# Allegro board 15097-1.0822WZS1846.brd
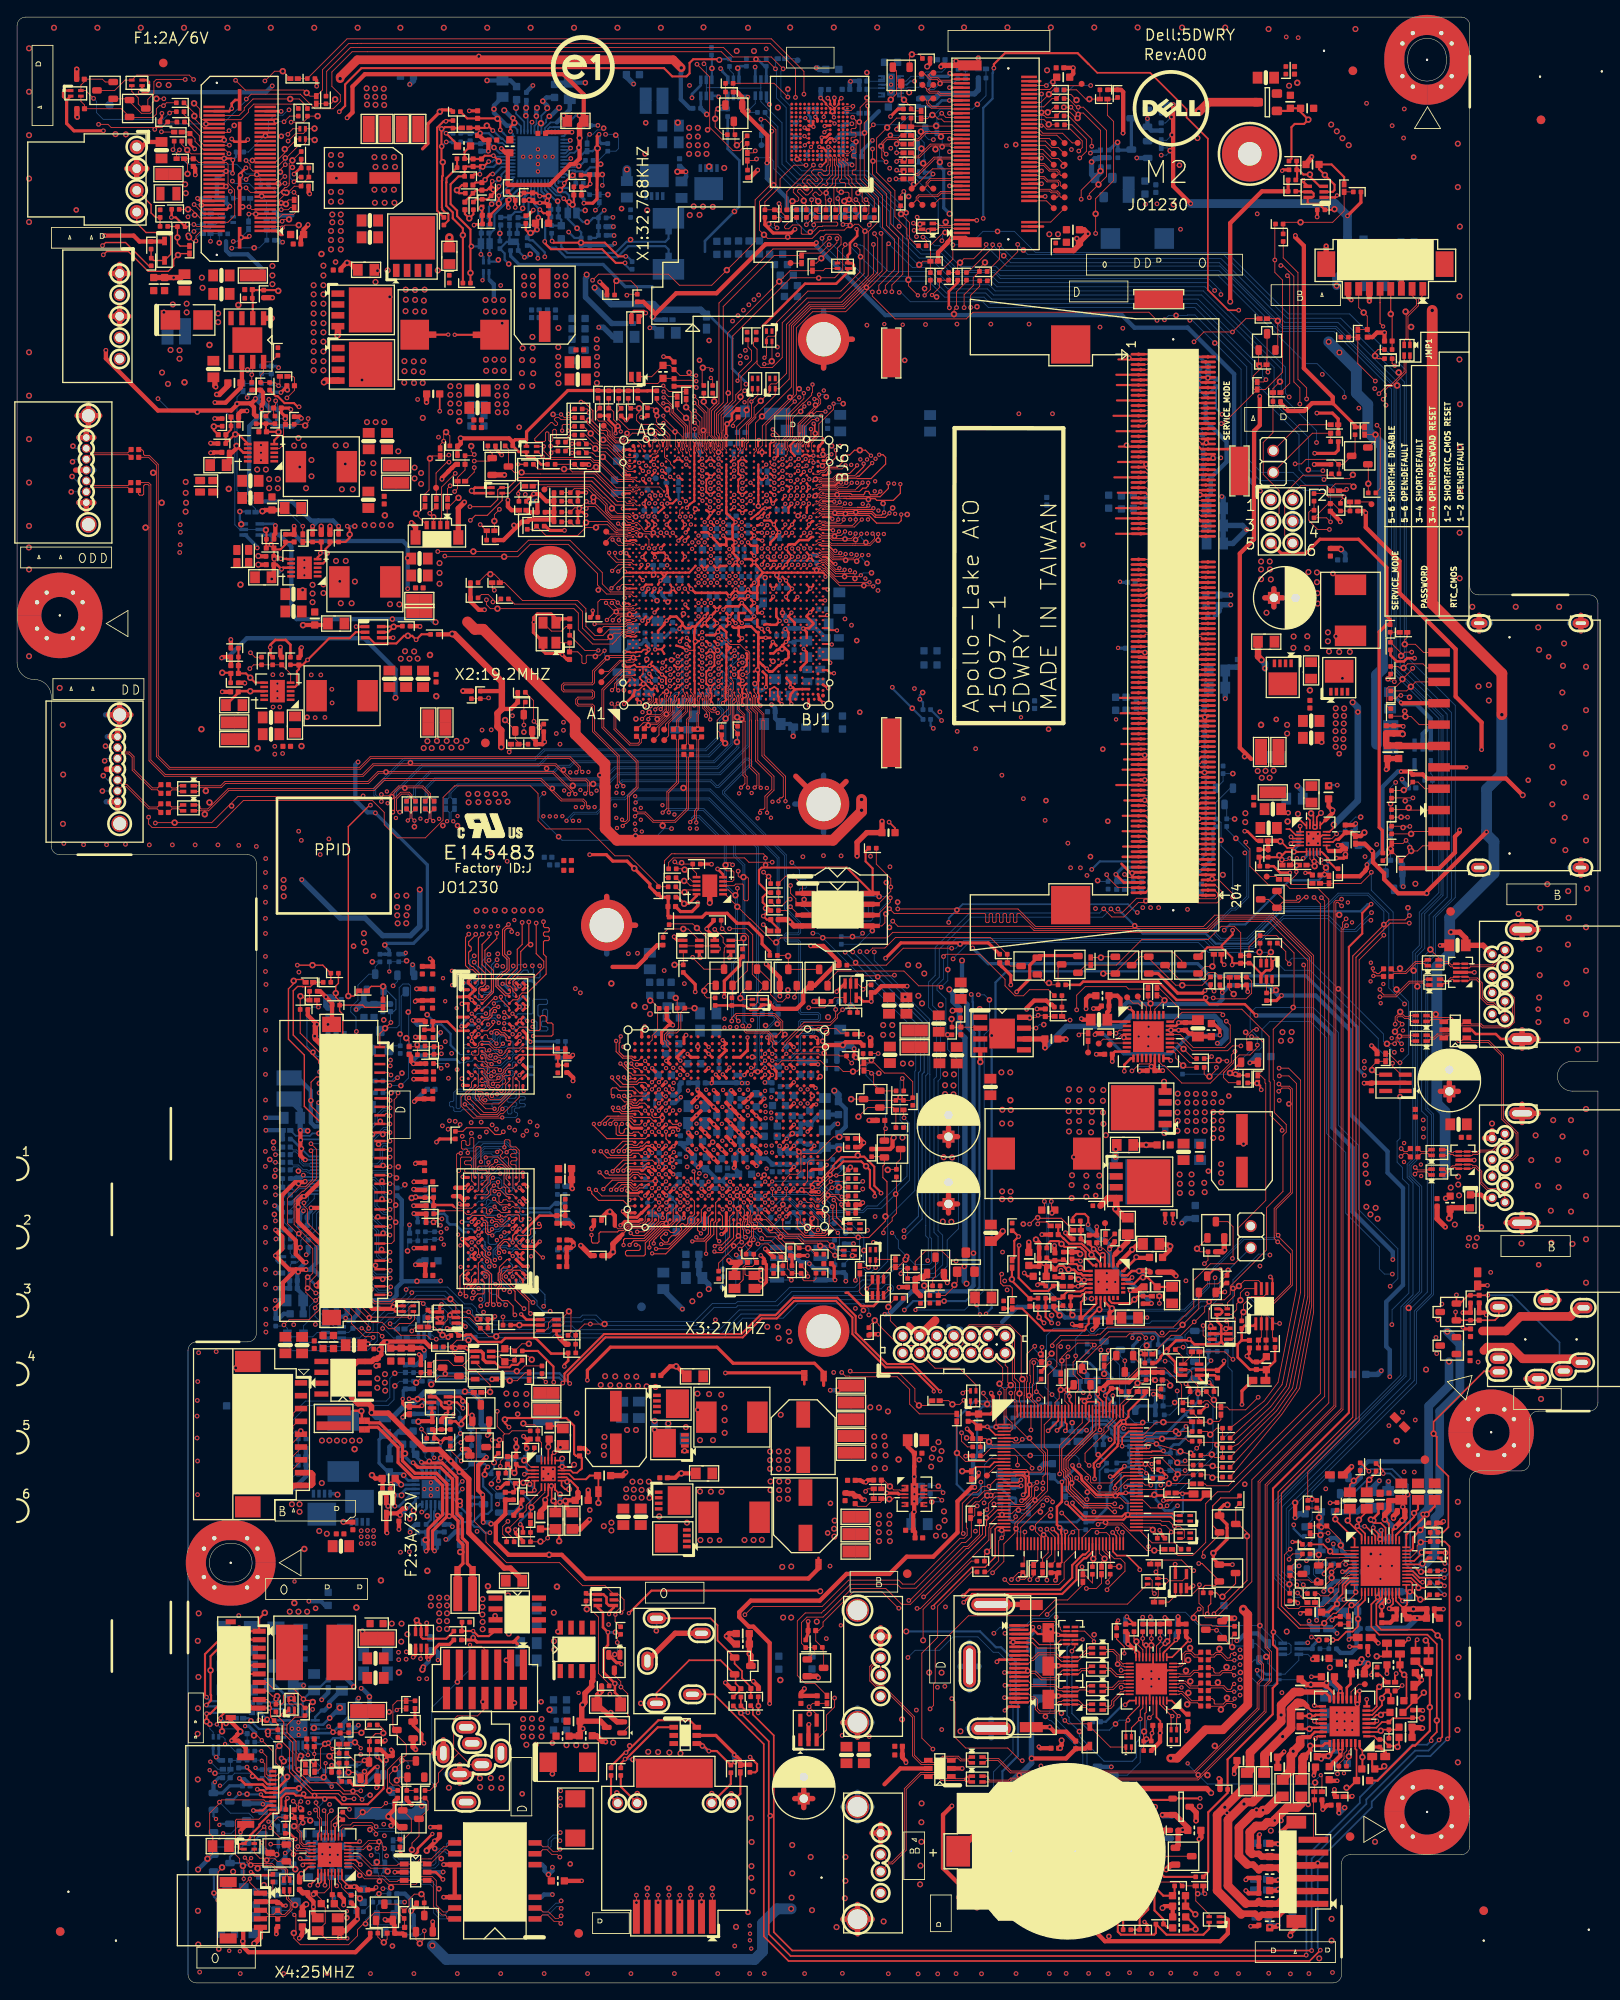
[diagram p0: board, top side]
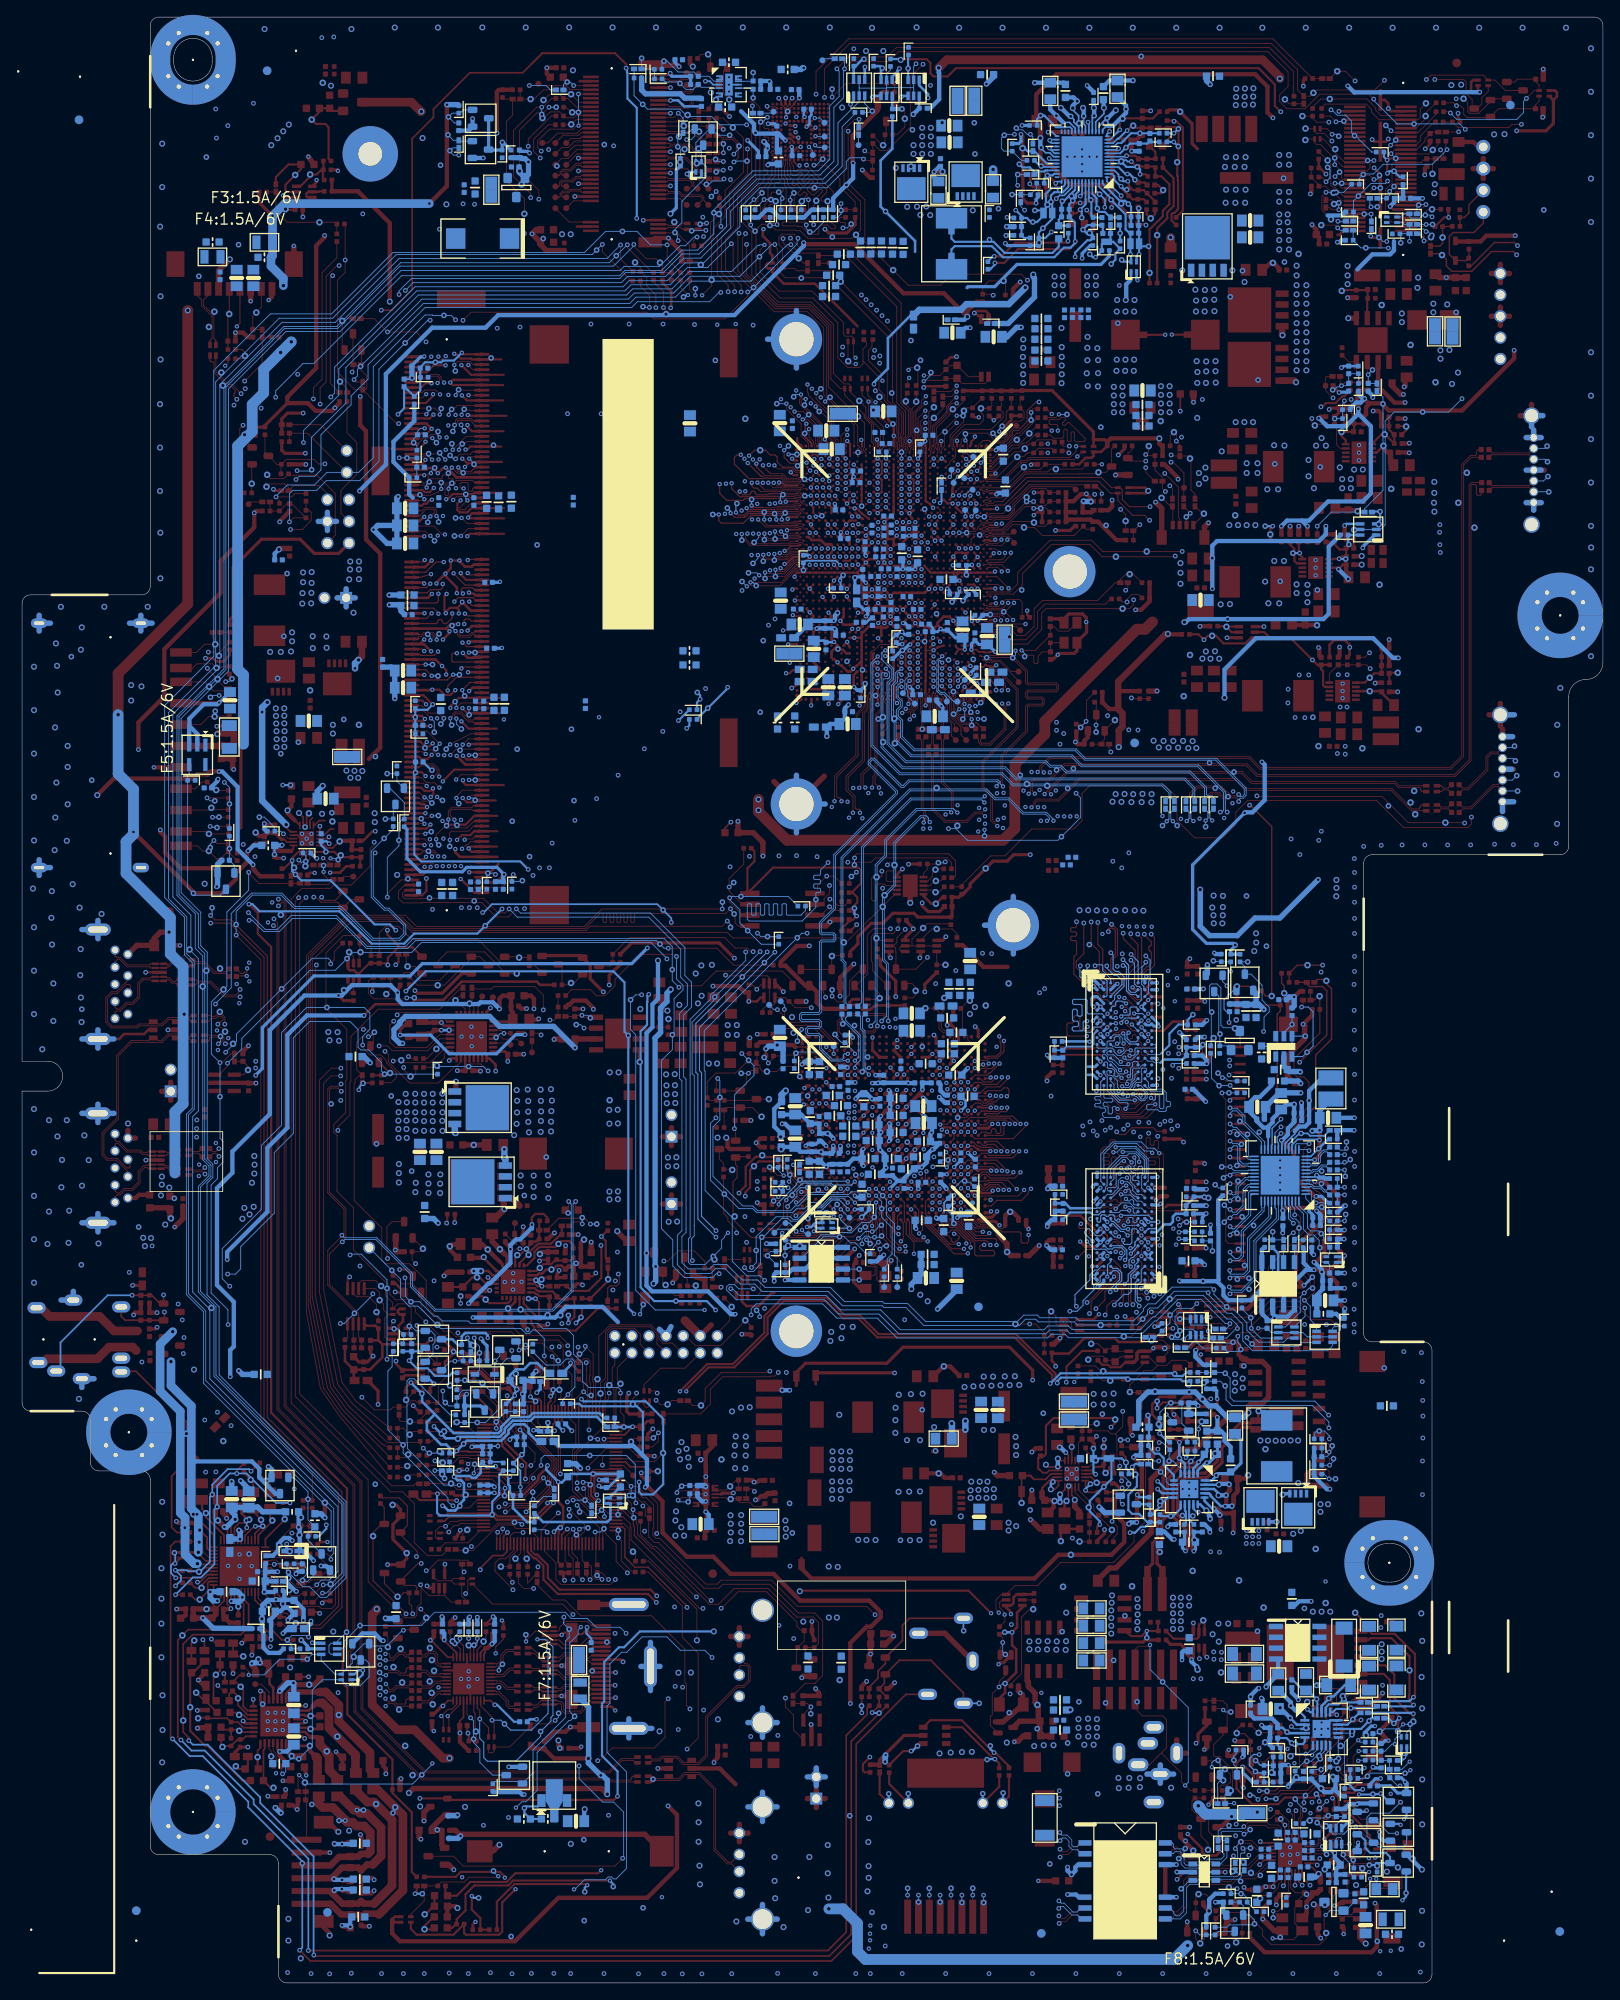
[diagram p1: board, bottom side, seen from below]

Outline 185 x 230 mm; copper layers: TOP, L2VCC, L3, L4, L5GND, BOTTOM. Coordinates in mm from the lower left corner of the outline.
Outline path: 0,229 0,154.5 arc(0.59,153.09) 2,152.5 arc(3.41,151.91) 4,150.5 4,133 arc(4.29,132.29) 5,132 27,132 arc(27.71,131.71) 28,131 28,76 arc(27.71,75.29) 27,75 21,75 arc(20.29,74.71) 20,74 20,1 arc(20.29,0.29) 21,0 154,0 arc(154.71,0.29) 155,1 155,14 arc(155.29,14.71) 156,15 169,15 arc(169.71,15.29) 170,16 170,58.9 arc(170.29,59.61) 171,59.9 176,59.9 arc(176.71,60.19) 177,60.9 177,65.9 arc(177.29,66.61) 178,66.9 184,66.9 arc(184.71,67.19) 185,67.9 185,104.34 182,104.34 arc(180.25,106.09) 182,107.84 185,107.84 185,161.4 arc(184.71,162.11) 184,162.4 171,162.4 arc(170.29,162.69) 170,163.4 170,229 arc(169.71,229.71) 169,230 1,230 arc(0.29,229.71) 0,229 ; 24.75,51.4 25.25,51.4 arc(27.5,49.15) 25.25,46.9 24.75,46.9 arc(22.5,49.15) 24.75,51.4 ; 162.75,225.25 arc(165,227.5) 167.25,225.25 167.25,224.75 arc(165,222.5) 162.75,224.75 162.75,225.25

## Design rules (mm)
constraint set DEFAULT: min track width 0.127, pair gap 0.102
net group AGND: nets CHG_AGND EC_AGND
net group AUDIO_IO_15: nets LINEOUT-L LINEOUT-R
net group AUDIO_SPK_L_C: nets SPKR_L+_C SPKR_L-_C
net group AUDIO_SPK_R_C: nets SPKR_R+_C SPKR_R-_C
net group AUDIO_SPKR_OUT_L: nets SPKR_OUT_L+ SPKR_OUT_L-
net group AUDIO_SPKR_OUT_R: nets SPKR_OUT_R+ SPKR_OUT_R-
net group CHARGER_4_5_MW-MW: nets AC_PROTECT AC_PROTECT_R
net group EMMC_RESET: nets EMMC_RESET# EMMC_RESET#_R
net group GPU_SMBUS: nets SMB_CLK_GPU SMB_DAT_GPU
net group INT_SERIRQ_CPU: nets INT_SERIRQ_CPU SER_IRQ
net group LAN_MDI2_DN: nets LAN_MDI2_DN LAN_MDI2_DN_R
net group LAN_MDI2_DP: nets LAN_MDI2_DP LAN_MDI2_DP_R
net group LAN_MDI3_DN: nets LAN_MDI3_DN LAN_MDI3_DN_R
net group LAN_MDI3_DP: nets LAN_MDI3_DP LAN_MDI3_DP_R
net group POWER_30_25: nets PWR_5V_HG1 PWR_VDDQ_HG
net group SATAHDR_RX_DN1: nets SATA__RXN1_C SATAHDR_RX_DN1
net group SATAHDR_RX_DP1: nets SATA__RXP1_C SATAHDR_RX_DP1
net group SATAHDR_TX_DN1: nets SATA__TXN1_C SATAHDR_TX_DN1
net group SATAHDR_TX_DP1: nets SATA__TXP1_C SATAHDR_TX_DP1
net group SIDE_USB3_TX0+: nets USB30_TX_CPU_P0 USB30_TX_CPU_P0_EMI
net group SIDE_USB3_TX0-: nets USB30_TX_CPU_N0 USB30_TX_CPU_N0_EMI
net group SIDE_USB3_TX1+: nets USB30_TX_CPU_P1 USB30_TX_CPU_P1_EMI
net group SIDE_USB3_TX1-: nets USB30_TX_CPU_N1 USB30_TX_CPU_N1_EMI
net group SIO_EUP: nets SIO_EUP_EN# SIO_EUP_EN#_G
net group SPI_CLK: nets KBC_SPI_CLK SPI_CLK_KBC_MUX
net group SPI_CLK-MW: nets ROM_SCLK ROM_SCLK_R
net group SVID-MW: nets VR_SVID_CLK VR_SVID_DATA
net group USB5_TP: nets USB_DN5 USB_DP5
net group USB_OC-MW: nets USBOC01 USBOC02
net group VGA_OTHER: nets +V_1P05_VGA_DISCHIG +V_1P35_VGA_DISCHG
net group AUDIO_AMP_10: nets AMP_SPKR_L AMP_SPKR_R SPKR_IN_L SPKR_IN_R TPA3131_LINN TPA3131_LINN_1 TPA3131_RINN TPA3131_RINN_1
net group AUDIO_AMP_15: nets PORTC_SPK_L PORTC_SPK_L_1 PORTC_SPK_R PORTC_SPK_R_1 TPA3131_GAIN TPA3131_GVDD TPA3131_MUTE TPA3131_PLIMIT
net group AUDIO_DMIC: nets AUD_DMIC_CLK AUD_DMIC_CLK_R AUD_DMIC_CLK_R_1 AUD_DMIC_DATA AUD_DMIC_DATA_R
net group AUDIO_HDA-15-MW: nets AUD_LINK_BCLK
net group AUDIO_HDA-MW: nets APU_SPKR AUD_BEEP_C AUD_BEEP_R AUD_LINK_RST_N AUD_LINK_RST_N_2 AUD_LINK_RST_N_R AUD_LINK_SDIN AUD_LINK_SDIN_1 AUD_LINK_SDIN_ST AUD_LINK_SDO AUD_LINK_SDO_1 AUD_LINK_SDO_N AUD_LINK_SYNC AZ_BCLK_M AZ_RST_N_M AZ_RST_R_M AZ_SDIN_M AZ_SDOUT_M AZ_SYNC_M BUZZER_SPKR_R PCH_AUD_RST_N PCH_AUD_RST_N_1 SENSE_B SLEEVE_G SPKR_DET_C
net group AUDIO_IO: nets AUD_GP3 EAPD_DEPOP HPOL_CON HPOR_CON HPOUT-JD HPOUT-L HPOUT-R LINE2-VREFO LINEOUT-JD LINEOUT_C-L LINEOUT_C-R LINEOUT_CON-L LINEOUT_CON-R MIC2-L MIC2-L-1 MIC2-R MIC2-R-1 MIC2-VREFO-L MIC2-VREFO-R
net group AUDIO_IO_REF: nets JDREF MIC-CAP VRP
net group AUDIO_POP-MW: nets TPA3131_FAULT# TPA3131_SD TPA3131_SD1#
net group AUDIO_SPK_CN: nets SPKR_L+_SNB SPKR_L-_SNB SPKR_R+_SNB SPKR_R-_SNB TPA3131_BSNL TPA3131_BSNR TPA3131_BSPL TPA3131_BSPR
net group CARDREADER-MW: nets SD_PWR_EN SD_PWR_EN_CPU# SD_PWR_EN_CPU#_R
net group CHARGER_4-5_MW-MW: nets AC_IN AC_IN_KBC#_R BAT_ALERT BAT_IN# BAT_IN#_1 CHG_ON# PD4405_A PD4405_K PQ4406_2 PQ4406_3 PQ4406_5 PQ4406_6 PQ4409_C PQ4409_E SYS_PRES
net group CLOCK-MW: nets CK_25M_SIO LPC_CLK0_R LPC_CLK1 LPC_CLK1_R SUSCLK SUSCLK_SIO_C XTAL19D2M_IN XTAL19D2M_OUT
net group CONERTER_4-5_MW-MW: nets LEDC_ISET LPF RT SSTCMP SSTCMP_1 STATUS
net group CONVERTER_10_10: nets ISEN1 ISEN2 ISEN3 ISEN4 ISW OZ554_PWM RTN1 RTN2 RTN3 RTN4
net group CONVERTER_20_10: nets LDR LDR_1 OZ554_VIN VREF
net group CPU_CRITITAL-MW: nets APU_PROCHOT# APU_PROCHOT#_R LPC_PME_N PMC_BATLOW#
net group DBG_I2C_SCL_LB: nets DBG_I2C_SCL_LB M1_SMB_CLK SMB0_CLK_MAIN SMB0_CLK_RESUME
net group DBG_I2C_SDA_LB: nets DBG_I2C_SDA_LB M1_SMB_DATA SMB0_DATA_MAIN SMB0_DATA_RESUME
net group DDR3_VREF: nets M_A_VREFCA_CPU M_A_VREFDQ_CPU PWR_VDDQ_VTTREF VREF_CA_DIMM1 VREF_DQ_DIMM1
net group DEEPSLEEP-MW: nets SUS_PWR_ACK_CPU
net group DP1_TXN0: nets DP1_TXN0 DP_CPU_TXN0 DP_CPU_TXN2 DRX0N
net group DP1_TXN1: nets DP1_TXN1 DP_CPU_TXN1 DP_CPU_TXN3 DRX1N
net group DP1_TXP0: nets DP1_TXP0 DP_CPU_TXP0 DP_CPU_TXP2 DRX0P
net group DP1_TXP1: nets DP1_TXP1 DP_CPU_TXP1 DP_CPU_TXP3 DRX1P
net group EC_CRITITAL: nets EC_SCI# EC_SMI# EC_SWI# ECRST# ECSCI#_KBC ECSMI#_KBC ECSWI#_KBC GPIO_11_SCI GPIO_12_SWI RTCRST_ON VNN_CTRL
net group EC_OTHER: nets EC_BEEP_GPIO EC_BEEP_GPIO_EC EC_DEBUG EC_PECI EDID_WC# EDID_WC_EC# PMIC_THERMTRIP#_EC RTC_DET# VD1_EN#
net group EC_PSL: nets PSL_IN1# PSL_IN2# PSL_OUT#
net group EC_PWR_12_12: nets EC_AVCC EC_VBKUP EC_VCC1V8_S5 EC_VCC3 EC_VDD3D3 EC_VSBY EC_VTT KBC_VCC
net group EC_SMB: nets EC_SMB_DATA
net group EC_SPI: nets EC_SPI_CS0_N EC_SPI_SI EC_SPI_SO
net group EC_SPI_CLK: nets EC_SPI_CLK
net group EC_VD: nets VD_IN1 VD_IN2 VD_OUT1# VD_OUT2#
net group EDP_PWM: nets BKLT_ADJ CPU_LVDS_BL_ADJ DPLVDS_PWMIN DPLVDS_PWMOUT LVDS_BL_ADJ RTD_LVDS_BL_ADJ SIO_LVDS_BL_ADJ
net group EMMC_CLK: nets EMMC_CLK
net group EMMC_CMD: nets EMMC_CMD
net group EMMC_DATA_0: nets EMMC_DATA_0
net group EMMC_DATA_1: nets EMMC_DATA_1
net group EMMC_DATA_2: nets EMMC_DATA_2
net group EMMC_DATA_3: nets EMMC_DATA_3
net group EMMC_DATA_4: nets EMMC_DATA_4
net group EMMC_DATA_5: nets EMMC_DATA_5
net group EMMC_DATA_6: nets EMMC_DATA_6
net group EMMC_DATA_7: nets EMMC_DATA_7
net group EMMC_POWER: nets EMMC_VDDI
net group EMMC_RCLK: nets EMMC_RCLK
net group EMMC_TP: nets EMMC_E9 EMMC_E10 EMMC_F10 EMMC_K10
net group FAN_PWM: nets CPU_FAN_CTRL_SIO CPU_FAN_TACH_SIO SYS_FAN_TACH1_1 SYS_FAN_TACH1_2 SYSTEM_FAN_PWM1_1
net group GPIO-MW: nets BATT_AMBER_LED# BATT_AMBER_LED#_C BATT_WHITE_LED# BATT_WHITE_LED#_C BIST_DISABLE BIST_DISABLE_1 BIST_EN BIST_EN_INV BIST_EN_SIO BIST_ENABLE BIST_ENABLE_1 BIST_PIN25 EAPD_DEPOP_1 EC_IMS JACK_PSID LVDS_DET_A* LVDS_DET_B* LVDS_PU_5 LVDS_PU_5_1 LVDS_PU_6 LVDS_PU_24 MINI_POWER_CTRL MPCIE_DISABLE_N NGFF_BT_DISABLE NGFF_DETECT_PCIE NGFF_DETECT_PCIE_C NGFF_DETECT_USB NGFF_DETECT_USB_C OSD_BIST_N OSD_DN OSD_DN_R OSD_MENU OSD_MENU_R OSD_UP OSD_UP_R PCB_VER_ID PSID_D PSID_D_1 PSID_G PW_CLEAR PW_CLEAR_H SOC_EXTSMI_N SPKR_DET WEBCAM_DET WEBCAM_DET_M
net group GPU_GPIO: nets GPIO1_FBVDDQCTL GPIO2_BL_PWM GPIO3_PPEN_R GPIO4_BLEN GPIO5_PWM_VID_BOOT_EN GPIO6_FB_CLAMP_TGL_REQ GPIO7_3D_STEREO GPIO8_OVERT# GPIO9_ALERT# GPIO10_MEM_VREF_CTL GPIO11_PWM_VID GPIO12_AC_DETECT GPIO13_NVVDD_PSI GPIO123_CPU
net group GPU_OTHER_4-6-MW: nets FB_VREF FBA_DEBUG0 FBA_DEBUG1 GC6_FB_EN GPIO_FB_CLAMP_GPU GPU_DMINUS GPU_DMINUS_G GPU_DPLUS GPU_DPLUS_G GPU_TESTMODE GPU_THERM_SHUTDOWN_N GPU_VCC3_CTL_2 GPU_WAKEB_CPU IFPA_IOVDD IFPAB_PLLVDD_1 IFPAB_PLLVDD_2 IFPB_IOVDD IFPC_IOVDD IFPC_PLLVDD_1 IFPC_PLLVDD_2 IFPD_IOVDD IFPD_PLLVDD_1 IFPD_PLLVDD_2 IFPE_IOVDD IFPEF_PLLVDD_1 IFPEF_PLLVDD_2 IFPF_IOVDD JTAG_TCLK JTAG_TDI JTAG_TDO JTAG_TMS JTAG_TRST PEX_TERMP PEX_TSTCLK_OUT PEX_TSTCLK_OUT# STRAP0 STRAP1 STRAP2 STRAP3 STRAP4 STRAP_REF0
net group GPU_VREF: nets DACA_VREF PWR_VGA_CORE_VREF PWR_VGA_CORE_VREF_1 PWR_VGA_CORE_VREF_2 VREFC_U20 VREFC_U21 VREFC_U22 VREFC_U23 VREFD_U20 VREFD_U21 VREFD_U22 VREFD_U23
net group GPU_ZQ: nets U15_ZQ U19_ZQ U35_ZQ U36_ZQ
net group HDMI1_DATA_IC_N0: nets HDMI1_DATA_IC_N0 HDMI_DATA_CPU_N0 HDMI_LANE0_IC_DN
net group HDMI1_DATA_IC_N1: nets HDMI1_DATA_IC_N1 HDMI_DATA_CPU_N1 HDMI_LANE1_IC_DN
net group HDMI1_DATA_IC_N2: nets HDMI1_DATA_IC_N2 HDMI_DATA_CPU_N2 HDMI_LANE2_IC_DN
net group HDMI1_DATA_IC_N3: nets HDMI1_DATA_IC_N3 HDMI_DATA_CPU_N3 HDMI_LANE3_DN HDMI_LANE3_IC_DN
net group HDMI1_DATA_IC_P0: nets HDMI1_DATA_IC_P0 HDMI_DATA_CPU_P0 HDMI_LANE0_DP HDMI_LANE0_IC_DP
net group HDMI1_DATA_IC_P1: nets HDMI1_DATA_IC_P1 HDMI_DATA_CPU_P1 HDMI_LANE1_DP HDMI_LANE1_IC_DP
net group HDMI1_DATA_IC_P2: nets HDMI1_DATA_IC_P2 HDMI_DATA_CPU_P2 HDMI_LANE2_DP HDMI_LANE2_IC_DP
net group HDMI1_DATA_IC_P3: nets HDMI1_DATA_IC_P3 HDMI_DATA_CPU_P3 HDMI_LANE3_IC_DP
net group HDMI_MW: nets CFG DCIN_EN DDCBUF DDPC_CTRL_CLK_CONN DDPC_CTRL_DATA_CONN EQ HDMI_CTRL_CLK HDMI_CTRL_CLK_CPU HDMI_CTRL_DATA HDMI_CTRL_DATA_CPU ISET PRE REXT
net group HPD-MW: nets CPU_HPD DDSP_C_HPD_CONN DP1_HPD DP_HPD DPLVDS_HPD HDM2_CPU_HPD HDMI2_HPD HDMI_DP2_HPD MODEL_ID_DET
net group LAN_OTHER_4-5-MW: nets LAN_RSET LANCLK_REQ_U_N RTL_ISOLATE_N RTL_ISOLATE_N_1 RTL_ISOLATE_N_2
net group LED_10_6: nets APU_SATA_LED_B APU_SATA_LED_N LAN_LEDACT_R# LINK_ACTIVITY_N LINK_PWR PB_IN_SW1 PCH_SATA_LED_1 PWR_LED_YELLOW_C PWR_LED_YELLOW_C2 SIO_GREEN_PWM SIO_HDD_LED SIO_HDD_LED_1 SIO_YELLOW SPEED_100*_CON SPEED_100_N SPEED_1000*_CON SPEED_1000_N SUS_LED_GREEN_C SUS_LED_GREEN_C2
net group LPC-MW: nets INIT_3V LPC_PME_N_R TPM_CLKRUN_N TPM_GPIO0 TPM_GPIO1 TPM_GPIO2 TPM_GPIO3 TPM_LCLK TPM_LPCPD_N TPM_PP TPM_RST_N TPM_SERIRQ
net group MIPI: nets CX_PMODE_PLRST_N DBG7_R DBG16_R DBG_H_PRDY_N DBG_H_PREQ_N DBG_H_TCK DBG_H_TDI DBG_H_TDO DBG_H_TMS DBG_H_TRST_N DBG_PMU_PLTRST_N DBG_PMU_PWRBTN_N DBG_PMU_RSTBTN_N DBG_PTI_CLK0 DBG_RSMRST_N DBG_TARGET_PRESENT_N DBG_UART_RXD DBG_UART_TXD DFX_MSR_STRAP GP_SPI0_FS1 TRST_PD
net group NGFF_CLK-MW: nets NGFF_CLKREQ0_N NGFF_CLKREQ1_N SUSCLK_NGFF
net group NGFF_OTHER-MW: nets NGFF_ALERT_N NGFF_PEWAKE0_N NGFF_POWER_CTRL_1 NGFF_POWER_CTRL_V2 NGFF_W_DISABLE1_N NGFF_W_DISABLE2_N SMB0_ALERT#_C
net group OCSILLATION-MW: nets LAN_XTALI LAN_XTALO PCH_RTCRST PCH_RTCRST_DOWN PCH_RTCRST_PULLUP PCH_RTCX1 PCH_RTCX2 PCH_SRTCRST_DOWN PCH_SRTCRSTB_PULLUP XTAL_OUTBUFF XTAL_SSFOUT
net group OTHERS-MW: nets 1D8V_EMMC_CT1 1D8V_EMMC_EN 3D3V_EMMC_CT2 3D3V_EMMC_EN AC_PRESENT_KBC AD_IA_R AD_JK1 AD_OFF_L ADAPTOR_PSID_R_R ALERT# AMD_RST#_L CLKA0_AND CLKA1_AND DIMM1_SA0 DIMM1_SA1 DISCHANGE_EN DPLVDS_HPD_1 GLAN_WAKE_CPU GLAN_WAKE_N GLAN_WAKE_N_LS GPIO34_CPU GPIO35_CPU GPIO36_VCCIO_LEVEL GPIO39_TXE_BPS GPIO40_CPU GPIO43_EMMC_BOOT GPIO44_SPI_BOOT GPIO47_DNXFW GPIO48_CPU GPIO78_SMB_LEVEL GPIO82_CPU GPIO88_PMU_LEVEL GPIO92_SMB_NRB GPIO104_CPU GPIO105_CPU GPIO110_LPC_LEVEL GPIO111_BBS GPIO112_CPU GPIO113_CPU GPIO117_CPU GPIO118_FLASH_OVR GPIO120_BIOS_SWAP GPIO121_CPU GPU_PEX_RST_HOLD GPU_PEX_RST_HOLD_GPU# H_PROCHOT_N_EC INTRUDER KBC_ON#_GATE KBC_ON#_GATE_L KBC_VCORF LVDS_PU_6_2 ME_UNLOCK ME_UNLOCK_1 ME_UNLOCK_2 ME_UNLOCK_3 MEM_MA_EVENT_L MIPI_PMODE NCT3956_OE#_MUX NGFF_WAKE_CPU NGFF_WAKE_N NGFF_WAKE_N_LS OSD_BIST_N_LS OSD_MENU_EC OSD_MENU_LS PCH_PCIECLKRQ0_N PCH_PCIECLKRQ1_N PCH_PCIECLKRQ3_N PCH_PCIECLKRQ3_N_B PCIE_WAKE1# PEX_RST_GPU_D# PLTRST#_CPU_D PLTRST#_EC_R PLTRST#_LPC PLTRST_N_1 PM_SLP_S0#_CPU PMIC_I2C_SCL PMIC_I2C_SDA PMIC_THERMTRIP# PMU_WAKE#_EMMC PNL0_BKLCTL PNL1_BKLCTL PURE_HW_SHUTDOWN#_R PWRBTN_APS PWRGD_3V_D S5_ENABLE SD_WP_BD_CPU SIO_EUP_EN_D SIO_GREEN_PWM_1 SIO_MEM_EVENT_L SIO_MEM_EVENT_L_B SIO_MEM_EVENT_L_C SIO_PWNBTN_N SLP_S0_APS SLP_S3_N_APS SLP_S4_N_APS SLP_S4_N_EC SOC_PWROK_CPU SRTCRST_APS SYS_PEX_RST_MON_GPU# SYS_PWRGD_G T_CRIT# THERM_SYS_SHDN# USB_EN_1 USB_EN_2 USB_OTGID USB_VBUSSNS V1P8A_S5_PG VCC3_CT2 VCC_CT1 VID_PLLVDD
net group PANEL_CONTROL: nets BKLT_EN BKLT_EN1 DPLVDS_BL_EN DPLVDS_PANEL_VCC LVDS_DET_B_C* PANEL_ON_1 PANEL_ON_2 PANEL_ON_3 PANEL_SEL1_CABLE PANEL_SEL1_CABLE_EC PANEL_SEL2_CABLE PANEL_SEL2_CABLE_EC PANEL_SEL3_CABLE PANEL_SEL3_CABLE_EC S_LVDS_BL_EN
net group PCIE_CLKREQ-MW: nets PCH_PCIECLKRQ2_N PCH_PCIECLKRQ2_N_1 PCH_PCIECLKRQ2_N_B PEX_CLKREQ_M PEX_CLKREQ_N
net group POWER: nets 3V_VA 19V_AMP_AVCC AD+_2 ADAPTOR_PSID_R AUD_DVDD AUD_REGREF AVCC33_2136 CBN CBP CPVEE DIGITAL_PU DPLVDS_PIN12 DPLVDS_PIN16 DVCC33_2136 EAPD_DEPOP_2 GND_AUD GPU_VCC3_CTL LED_5VSB OSD_BIST_N_1 PWRCN_DET_N PWRCN_DET_N_C SWR_LX SWR_V12 V_3P0_BAT_VREG V_5_CODEC VBAT1 VBAT1_R VREF_1 VREG_PCIAUX_PCH VREG_PCIAUX_PCH_1
net group POWER_10_10: nets 1D8V_S0_EN 1D8V_S0_EN1 1D8V_S0_EN2 1D8V_S0_EN_G 1D8V_SPI 1D35V_S3_PWRGD 1117_ADJ AD+_G_1 AD+_G_2 AD_IA AD_IA_HW1 AD_IA_HW2 EC_V_3P3_A GPU_ALLPWR NCP81172_FB1 PSYS PWR_1D05V_EN PWR_1D05V_FB PWR_1D05V_FB_N PWR_1D24V_EN PWR_1D24V_FB PWR_1D24V_FB_N PWR_1D24V_PG PWR_1D35V_FB PWR_1D35V_FB_N PWR_1P15V_PG_L PWR_3D3V_CS2 PWR_3D3V_FB2 PWR_3D3V_LDO3 PWR_5V_BOOT1_A PWR_5V_FB1 PWR_5V_LDO5 PWR_ALERT# PWR_CHG_ACDET PWR_CHG_ILIM PWR_CHG_NC PWR_SCLK_A PWR_SDIO PWR_V1P8A_FB PWR_V1P24A_PG_L PWR_VCCGI_COMP PWR_VCCGI_COMPA PWR_VCCGI_CSCOMP PWR_VCCGI_CSP1 PWR_VCCGI_CSREF PWR_VCCGI_CSSUM PWR_VCCGI_DIFFOUT PWR_VCCGI_EN PWR_VCCGI_EN_PH PWR_VCCGI_FB PWR_VCCGI_FBA PWR_VCCGI_ICCMAX PWR_VCCGI_ILIM PWR_VCCGI_IOUT PWR_VCCGI_NTC PWR_VCCGI_TSENSE PWR_VCCGI_VR_RDY PWR_VCCGI_VR_RDY1 PWR_VCCGI_VRMP PWR_VCCGI_VSN PWR_VCCGI_VSNA PWR_VCCGI_VSP PWR_VCCGT_ILIM_NTC PWR_VDDQ_FB PWR_VGA_CORE_COMP PWR_VGA_CORE_COMP_1 PWR_VGA_CORE_FB PWR_VGA_CORE_FBRTN PWR_VGA_CORE_FS PWR_VGA_CORE_PGOOD PWR_VGA_CORE_PSI PWR_VGA_CORE_PVCC PWR_VGA_CORE_REFIN PWR_VGA_CORE_SENSE+_1 PWR_VGA_CORE_TALERT# PWR_VGA_CORE_TSNS PWR_VGA_CORE_VID PWR_VGA_CORE_VIDBUF PWR_VGA_VRAM_POK PWR_VGA_VRAM_POK_B_1 PWR_VNN_COMP PWR_VNN_COMPA PWR_VNN_CSN_NTC PWR_VNN_CSP1B PWR_VNN_ILIM PWR_VNN_IOUT PWR_VNN_PWM PWR_VNN_VSN PWR_VNN_VSP PWR_VNN_VSPA PWR_VNN_VSPA_R PWR_VR_HOT# V_3P3_A V_5P0_A VNN_VCC_SENSE VNN_VSS_SENSE
net group POWER_10_15: nets BOOT_HALT_N
net group POWER_12_12: nets 3D3V_AUX_S5_MUX BUFRST_N PQ4206_D PWR_3D3V_BOOT2 PWR_3D3V_BOOT2_A
net group POWER_20_10: nets 3D3VDD_TPM PWR_1D05V_SVIN PWR_1D24V_SVIN PWR_VDDQ_VDD PWR_VDDQ_VDDQ PWR_VDDQ_VID PWR_VGA_CORE_BOOT1_1 PWR_VGA_CORE_LGATE1 PWR_VGA_CORE_SNB PWR_VGA_CORE_VCC VCC_1P24_A1_R
net group POWER_20_20: nets PWR_1D05V_SN PWR_1D24V_SN PWR_3D3V_FB2_A PWR_3D3V_SN PWR_5V_BOOT1 PWR_5V_BYP1 PWR_5V_FB1_A PWR_5V_SN PWR_CORE_BOOT PWR_CORE_BOOT_A PWR_CORE_SN PWR_VGA_CORE_BOOT1 PWR_VNN_BOOT PWR_VNN_BOOTA PWR_VNN_SN
net group POWER_25_20: nets CORE_PLLVDD DACA_VDD FB_CAL_PD_VDDQ FB_CAL_PU_GND FB_CAL_TERM_GND
net group POWER_50_10: nets 1D8V_S5_D 1D24V_DSI_CSI 1D24V_GLML 1D24V_S5_D 1P05V_S5_D BQ24737_REGN DC_IN_D PWR_1D35V_SVIN PWR_CHG_BTST PWR_CHG_BTST_1 PWR_CHG_CMPIN PWR_CHG_CMPIN_R PWR_CHG_CMPIN_RR PWR_CHG_VCC PWR_VCORE_VNN_D SB3V_D SP_PLLVDD
net group POWER_100_10: nets DCBATOUT_RT6575_1
net group POWER_OTHER: nets 3V3AUX ALL_PWRGD_2 PURE_HW_SHUTDOWN# PWR_CHG_AD_OFF PWR_CHG_AD_OFF_R PWR_VDDQ_CS PWR_VDDQ_TON PWRBTN_N_R PWRGD_3V_G1 PWRGD_3V_G2 PWRGD_3V_N
net group POWER_PHASE: nets PWR_CHG_HIDRV PWR_CHG_LODRV PWR_CORE_HG1 PWR_CORE_LG1 PWR_VGA_CORE_UGATE1 PWR_VGA_CORE_UGATE1_R PWR_VNN_HG
net group PWR-EN_MW-MW: nets 1D8V_S0_EN_R DGPU_PWR_EN# GPU_1D05V_EN GPU_1D05V_FB GPU_1D05V_VGA_EN PWR_3D3V_EN2 PWR_5V3V_EMN_R PWR_5V_EN1 PWR_V1P8A_EN PWR_VDDQ_EN PWR_VGA_CORE_EN PWR_VTT_EN SIO_EUP_EN#_L SIO_EUP_EN#_R SIO_GPU_EN_C SIO_GPU_EN_LS SLP_S0_N SLP_S3_N SLP_S4_N VCC3_EN VCC_EN VGA_CORE_DISCHG VTT_EN VTT_EN_R
net group PWRGD-RST-MW: nets 1P05V_PG 1P05V_PG_EC 3V_5V_POK AC_PRESENT_CPU APU_PWNBTN_N APU_PWNBTN_N_R DDR3_DRAMRST_N DDR3_DRAMRST_N_A_1 GPU_1D05V_PG LAN_DISABLE_N LAN_DISABLE_N_1 LAN_DISABLE_N_2 LAN_DISABLE_N_3 LAN_DISABLE_N_4 LAN_DISABLE_V3 OZ554_ENA PCIE_RST# PEX_RST_GPU PLT_RST#_CPU PLTRST*_SIO PLTRST_LAN_N PLTRST_N PLTRST_N_1A PLTRST_N_R PLTRST_SL_N PM_SLP_S3#_CPU PM_SLP_S4#_CPU PMC_SUS_STAT PSTBTN_N PSTBTN_N_APS PWR_3D3V_5V_PG PWR_5V_CS1 PWR_V1P8A_PG PWRBTN_N PWRGD_3V PWRGD_3V_B PWRGD_3V_B_1 PWRGD_3V_C PWRGD_3V_LL PWROK3_1_R PWROK3_2_R RSMRST#_KBC_MUX RSMRST*_R RSMRST_APS RSMRST_N SIO_GPU_EN SIO_GPU_RST SIO_GPU_RST_C SIO_GPU_RST_LS SLP_S3_N_EC SUS_PWR_ACK_CPU_R SYS_PWRGD V1P8A_S5_PG_EC WAKE_N_APU
net group SATAHDR_RX_DN0: nets SATA__RXN0_C SATAHDR_RX_DN0 SATAHDR_RX_DN0_EMI
net group SATAHDR_RX_DP0: nets SATA__RXP0_C SATAHDR_RX_DP0 SATAHDR_RX_DP0_EMI
net group SATAHDR_TX_DN0: nets SATA__TXN0_C SATAHDR_TX_DN0 SATAHDR_TX_DN0_EMI
net group SATAHDR_TX_DP0: nets SATA__TXP0_C SATAHDR_TX_DP0 SATAHDR_TX_DP0_EMI
net group SD_CD_BD: nets SD_CD_BD_CPU
net group SD_CLK_BD: nets SD_CLK_BD_CPU
net group SD_CMD_BD: nets SD_CMD_BD_CPU
net group SD_DATA0_BD: nets SD_DATA0_CPU
net group SD_DATA1_BD: nets SD_DATA1_CPU
net group SD_DATA2_BD: nets SD_DATA2_CPU
net group SD_DATA3_BD: nets SD_DATA3_CPU
net group SIDE_USB3_RX0+: nets USB30_RX_CPU_P0
net group SIDE_USB3_RX0-: nets USB30_RX_CPU_N0
net group SIDE_USB3_RX1+: nets USB30_RX_CPU_P1
net group SIDE_USB3_RX1-: nets USB30_RX_CPU_N1
net group SIO_IT8732-MW: nets EC_HDMI_PD_N IMS SW_ON_N_SIO
net group SIO_OTHERS-MW: nets AC_OK# ADAPTOR_PSID_SIO INT_SERIRQ_OE PD_N
net group SMBUS-MW: nets BATA_SCL_1 BATA_SDA_1 DPLVDS_EDIDCLK DPLVDS_EDIDCLK_C DPLVDS_EDIDSDA DPLVDS_EDIDSDA_C DPLVDS_FWCLK DPLVDS_FWSDA DPLVDS_ISPCLK DPLVDS_ISPDAT I2CC_SCL_PU I2CC_SDA_PU I2CS_SCL_G I2CS_SDA_G ISP_CLK1 ISP_DAT1 NCT_CLK NCT_DATA PWR_CHG_IOUT SIO_SMCLK0 SIO_SMCLK0_D SIO_SMDAT0 SIO_SMDAT0_D SMB0_ALERT# SMB0_CVT_CLK SMB0_CVT_DATA SMBUS_ISP SMBUS_ISP_G
net group SPI-MW: nets FWH_ID0
net group SPI_CLK_CPU_MUX: nets SPI_CLK_CPU_MUX SPI_CLK_N_CPU SPI_CLK_ROM SPI_CLK_ROM_CPU SPI_CLK_ROM_KBC SPI_CLK_ROM_MUX
net group SPI_CS0_N_ROM: nets SPI_CS0_N_ROM_CPU SPI_CS0_R_CPU SPI_CS_CPU_MUX SPI_CS_ROM_MUX
net group SPI_DATA: nets KBC_SPI_CS0_N KBC_SPI_DATAIN KBC_SPI_DATAOUT ROM_CS* ROM_CS_R* ROM_SI ROM_SI_R ROM_SO SPI_CS0_N_ROM_KBC SPI_CS_KBC_MUX SPI_DATAIN_N_CPU SPI_DATAIN_ROM SPI_DATAOUT_N_CPU SPI_DATAOUT_ROM SPI_IO2_N_CPU SPI_IO2_ROM SPI_IO3_N_CPU SPI_IO3_ROM
net group SVID0_CLK_CPU: nets SVID0_CLK_CPU_R
net group SVID0_DATA_ALERT: nets SVID0_ALERT#_CPU_R SVID0_DATA_CPU_R VR_SVID_ALERT#
net group TP-MW: nets AC_IN_KBC# SYNC TP_DET TP_NGFF_COEX1 TP_NGFF_COEX2 TP_NGFF_COEX3 TP_NGFF_LED1 TP_NGFF_LED2 TP_NGFF_MLDIR
net group TRANSFORNER_20_10: nets XRF_TDC2
net group UART: nets LPSS_UART1_RXD LPSS_UART2_CTS# LPSS_UART2_RTS# LPSS_UART2_RXD LPSS_UART2_TXD
net group WLAN_CLINK_MW-MW: nets CLINK_CLK_LAN CLINK_DATA_LAN CLINK_RST_LAN_N
net group XDP-MW: nets DBG0 DBG1 DBG2 DBG3 DBG4 DBG5 DBG6 DBG7 DBG16 TAP_PRDY# TAP_PREQ# XDP_H_TDO XDP_H_TRST_N
net group XTAL_GPU_27MHZ: nets XTALOUT_GPU

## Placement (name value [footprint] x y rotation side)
AFTP1  AFTE14P-GP  [AFTE14P-75]  43.92 26.54 0 top
BAT2  ACES-CON9-10-GP  [51202-00901-W01-U]  27 64.2 270 top
BT1  BAT-AAA-BAT-034-K01-GP  [AAA-BAT-034-K01]  116.34 15.4 180 top
C1  SCD1U16V2KX-3DLGP  [C402H22]  122.04 224.07 90 top
C2  SCD1U16V2KX-3DLGP  [C402H22]  149.49 223.77 0 top
C3  SC10U6D3V3MX-DL-GP  [C603H36]  122.42 222.97 270 top
C4  SC10U10V5KX-2GP  [C805H54]  146.13 222.91 270 top
C5  SCD1U50V3KX-GP  [C603H36]  149 220.09 180 top
C6  SCD1U50V3KX-DL-GP  [C603H35]  150.96 219.33 90 top
C7  SCD1U16V2KX-3DLGP  [C402H22]  20.22 215.93 0 top
C8  SC10U25V5KX-DL-GP  [C805H58]  16.9 214.43 180 top
C9  SCD1U16V2KX-3DLGP  [C402H22]  20.61 212.97 0 top
C10  SCD1U50V3KX-GP  [C603H36]  151.6 212.76 270 top
C11  SC2D2U10V3KX-1DLGP-U  [C603H36]  123.56 205.12 90 top
C12  SC10U6D3V3MX-DL-GP  [C603H36]  32.77 204.56 90 top
C13  SC10U6D3V3MX-DL-GP  [C603H36]  123.56 203.65 270 top
C14  SCD1U16V2KX-3DLGP  [C402H22]  32.76 203.45 90 top
C15  SC10U10V5KX-2DLGP  [C805H50]  19.59 198.96 180 top
C16  SC1U50V3KX-1-GP  [C603H36]  15.99 198.76 180 top
C17  SC10U6D3V3MX-DL-GP  [C603H36]  17.26 198.76 180 top
C18  SC100P50V2JN-3GP  [C402H22]  160.47 192.1 90 top
C19  SC1U10V2KX-1DLGP  [C402H22]  65.85 191.07 90 top
C20  SC22U6D3V5MX-2DLGP  [C805H54]  65.61 189.63 90 top
C21  SC2D7P50V2CN-3-GP  [C402H22]  76.88 189.2 180 top
C22  SC22U6D3V5MX-2DLGP  [C805H54]  65.61 187.6 90 top
C23  SC2D7P50V2CN-3-GP  [C402H22]  76.88 187.25 0 top
C24  SC22U6D3V5MX-2DLGP  [C805H54]  53.88 186.31 270 top
C25  SC22U6D3V5MX-2DLGP  [C805H54]  53.88 184.28 270 top
C26  SCD1U16V2KX-3DLGP  [C402H22]  84.37 183.65 180 top
C27  SC1U10V2KX-1DLGP  [C402H22]  53.9 182.86 270 top
C28  SC1U10V2KX-1DLGP  [C402H22]  53.89 181.98 270 top
C29  SC1U10V2KX-1DLGP  [C402H22]  154.16 181.32 90 top
C30  SCD01U50V2KX-1DLGP  [C402H22]  13.79 179.41 270 top
C31  SCD01U50V2KX-1DLGP  [C402H22]  13.79 178.49 270 top
C32  SC47P50V2JN-3GP  [C402H22]  51.98 177.67 270 top
C33  SCD01U50V2KX-1DLGP  [C402H22]  13.75 175.53 270 top
C34  SCD01U50V2KX-1DLGP  [C402H22]  13.75 174.62 270 top
C35  SC1U10V2KX-1DLGP  [C402H22]  153.68 172.63 0 top
C36  SC3D3P50V2CN-DL-GP  [C402H22]  64.67 159.15 0 top
C37  SC3D3P50V2CN-DL-GP  [C402H22]  64.65 155.29 180 top
C38  SCD1U16V2KX-3DLGP  [C402H22]  160.22 146.64 0 top
C39  SCD1U16V2KX-3DLGP  [C402H22]  161.12 146.64 0 top
C40  SCD1U16V2KX-3DLGP  [C402H22]  72.49 146.29 0 top
C41  SCD1U16V2KX-3DLGP  [C402H22]  73.4 146.29 0 top
C42  SCD22U10V2KX-2-GP  [C402H22]  76.83 146.24 0 top
C43  SCD22U10V2KX-2-GP  [C402H22]  79.21 146.24 0 top
C44  SCD22U10V2KX-2-GP  [C402H22]  80.1 146.23 0 top
C45  SCD22U10V2KX-2-GP  [C402H22]  77.71 146.23 0 top
C46  SCD1U16V2KX-3DLGP  [C402H22]  78.03 144.17 0 top
C47  SCD1U16V2KX-3DLGP  [C402H22]  78.91 144.17 0 top
C48  SC4D7U6D3V3KX-DLGP  [C603H36]  161.68 144.01 180 top
C49  SC4D7U6D3V3KX-DLGP  [C603H36]  160.36 144 180 top
C50  SCD01U50V2KX-1DLGP  [C402H22]  17.27 140.19 270 top
C51  SCD01U50V2KX-1DLGP  [C402H22]  17.27 139.18 270 top
C52  SC1U10V2KX-1DLGP  [C402H22]  144.72 138.26 0 top
C53  SCD01U50V2KX-1DLGP  [C402H22]  17.26 137.96 270 top
C54  SCD01U50V2KX-1DLGP  [C402H22]  17.26 136.94 270 top
C55  SC22U6D3V5MX-2DLGP  [C805H54]  75.62 82.14 180 bottom
C56  SCD1U16V2KX-3DLGP  [C402H22]  76.61 125.93 90 top
C57  SCD1U16V2KX-3DLGP  [C402H22]  88.64 124.41 270 top
C58  SC100P50V2JN-3DLGP  [C402H22]  143.2 119.74 0 top
C59  SC10U10V5KX-2DLGP  [C805H50]  168.56 121.4 90 top
C60  SCD1U16V2KX-3DLGP  [C402H22]  160.36 118.64 90 top
C61  SCD1U16V2KX-3DLGP  [C402H22]  47.42 118.49 180 top
C62  SCD1U16V2KX-3DLGP  [C402H22]  48.64 118.49 180 top
C63  SCD1U16V2KX-3DLGP  [C402H22]  160.36 117.75 90 top
C64  SCD1U16V2KX-3GP  [C402H22]  142.34 116.69 90 top
C65  SC1U10V2KX-1DLGP  [C402H22]  48.08 116.3 270 top
C66  SC1U10V2KX-1DLGP  [C402H22]  48.62 114.5 180 top
C67  SC1U10V2KX-1DLGP  [C402H22]  47.43 114.49 180 top
C68  SC22U6D3V5MX-2DLGP  [C805H54]  102.04 114.35 180 top
C69  SC22U6D3V5MX-2DLGP  [C805H54]  104.07 114.35 180 top
C70  SCD1U16V2KX-3DLGP  [C402H22]  127.34 114.29 270 top
C71  SC1U50V3KX-1-GP  [C603H36]  77.14 88.67 0 bottom
C72  SC10U10V5KX-2DLGP  [C805H50]  126.61 112.69 270 top
C73  SCD1U16V2KX-3DLGP  [C402H22]  48.21 112.47 270 top
C74  SCD1U16V2KX-3DLGP  [C402H22]  136.74 111.91 180 top
C75  SC10U10V5KX-2DLGP  [C805H50]  138.18 111.68 180 top
C76  SCD01U50V2KX-1DLGP  [C402H22]  99.45 109.7 90 top
C77  SCD01U25V2KX-3LLGP  [C402H22]  45.87 109.09 0 top
C78  SCD1U16V2KX-3DLGP  [C402H22]  127.72 108.66 270 top
C79  SC22U6D3V5MX-2DLGP  [C805H54]  102.14 108.58 0 top
C80  SCD1U16V2KX-3DLGP  [C402H22]  63.73 108.35 90 top
C81  SCD1U16V2KX-3GP  [C402H22]  159.15 108.27 180 top
C82  SCD1U16V2KX-3DLGP  [C402H22]  132.7 106.73 270 top
C83  SC1U10V2KX-1DLGP  [C402H22]  48.29 106.6 270 top
C84  SCD1U16V2KX-3DLGP  [C402H22]  48.29 105.74 270 top
C85  SC1U10V2KX-1DLGP  [C402H22]  158.49 104.82 180 top
C86  SC1U10V2KX-1DLGP  [C402H22]  48.64 103.88 0 top
C87  SCD1U16V2KX-3DLGP  [C402H22]  47.63 103.87 0 top
C88  SCD1U16V2KX-3DLGP  [C402H22]  163.62 101.75 0 top
C89  SC100P50V2JN-3DLGP  [C402H22]  101.1 100.91 90 top
C90  SC10U10V5KX-2DLGP  [C805H50]  168.69 100.46 90 top
C91  SCD1U16V2KX-3GP  [C402H22]  169.45 98.93 270 top
C92  SCD1U16V2KX-3DLGP  [C402H22]  163.49 97.62 270 top
C93  SCD1U50V3KX-DL-GP  [C603H35]  138.41 97.23 180 top
C94  SCD1U16V2KX-3DLGP  [C402H22]  163.48 96.65 270 top
C95  SC1U10V2KX-1DLGP  [C402H22]  47.68 95.49 180 top
C96  SC10U6D3V3MX-DL-GP  [C603H36]  64.12 95.26 90 top
C99  SC1U10V2KX-1DLGP  [C402H22]  166.17 91.31 0 top
C100  SC10U6D3V3MX-DL-GP  [C603H36]  64.12 93.98 90 top
C101  SC1U10V2KX-1DLGP  [C402H22]  48.19 93.73 270 top
C103  SCD1U16V2KX-3DLGP  [C402H22]  48.31 90.93 270 top
C104  SCD1U16V2KX-3DLGP  [C402H22]  63.17 89.33 0 top
C108  SC22U6D3V5MX-2DLGP  [C805H54]  113.95 87.76 0 top
C110  SCD1U16V2KX-3DLGP  [C402H22]  63.9 86.92 90 top
C111  SCD1U16V2KX-3DLGP  [C402H22]  63.9 86 90 top
C112  SCD1U16V2KX-3DLGP  [C402H22]  48.26 85.97 270 top
C113  SC1U10V2KX-1DLGP  [C402H22]  63.88 84.94 90 top
C114  SC15P50V2JN-DL-GP  [C402H22]  85.03 84.3 270 top
C115  SC15P50V2JN-DL-GP  [C402H22]  86.98 84.3 90 top
C116  SCD1U16V2KX-3-LL-GP  [C402H22]  94.85 84.15 270 top
C117  SC1U10V2KX-1DLGP  [C402H22]  48.21 84.02 270 top
C118  SC1U10V2KX-1DLGP  [C402H22]  63.88 83.82 90 top
C119  SC1U10V2KX-1DLGP  [C402H22]  48.21 82.77 270 top
C120  SCD01U25V2KX-3DLGP  [C402H22]  104.66 81.41 90 top
C121  SC100P50V2JN-3DLGP  [C402H22]  171.1 80.01 0 top
C122  SCD1U16V2KX-3DLGP  [C402H22]  107.81 79.98 0 top
C123  SC100P50V2JN-3DLGP  [C402H22]  171.1 77.98 180 top
C124  SC100P50V2JN-3DLGP  [C402H22]  170.09 76.07 180 top
C125  SC2200P50V2KX-2DLGP  [C402H22]  145.71 75.21 90 top
C126  SCD1U16V2KX-3DLGP  [C402H22]  144.21 74.73 0 top
C127  SC470P50V2KX-3DLGP  [C402H22]  145.71 74.3 90 top
C128  SCD1U25V3KX-DLGP  [C603H36]  43.73 73.52 180 top
C129  SCD1U25V3KX-DLGP  [C603H36]  44.95 73.52 180 top
C130  SCD1U25V3KX-DLGP  [C603H36]  46.14 73.52 180 top
C131  SC100P50V2JN-3DLGP  [C402H22]  170.04 73.25 0 top
C132  SC10U6D3V3MX-DL-GP  [C603H36]  146.19 72.5 180 top
C133  SCD1U16V2KX-3DLGP  [C402H22]  145.03 72.21 180 top
C134  SCD1U16V2KX-3DLGP  [C402H22]  140.48 71.23 180 top
C135  SCD1U10V2KX-5GP  [C402H22]  133.1 71 0 top
C136  SCD1U16V2KX-3DLGP  [C402H22]  134.01 70.99 180 top
C137  SCD1U16V2KX-3DLGP  [C402H22]  127.61 69.56 270 top
C138  SCD1U16V2KX-3DLGP  [C402H22]  137.96 66.8 90 top
C139  SCD1U10V2KX-5DLGP  [C402H22]  111.3 66.15 180 top
C140  SC2D2U10V3KX-1DLGP-U  [C603H36]  112.51 65.8 180 top
C141  SC220P50V2KX-3GP  [C402H22]  112.28 63.68 270 top
C142  SC10U10V5KX-2GP  [C805H54]  105.19 63.5 270 top
C143  SCD1U16V2KX-3DLGP  [C402H22]  105.44 61.98 270 top
C144  SC1U6D3V2KX-DLGP  [C402H22]  100.69 58.83 270 top
C145  SC10U10V5KX-2DLGP  [C805H50]  161.98 57.48 180 top
C146  SC10U10V5KX-2DLGP  [C805H50]  163.94 57.48 0 top
C147  SC10U10V5KX-2DLGP  [C805H50]  165.9 57.48 0 top
C148  SCD1U16V2KX-3DLGP  [C402H22]  160.54 56.87 0 top
C149  SC2D2U10V3KX-1DLGP-U  [C603H36]  159.51 56.53 180 top
C150  SC1U6D3V2KX-DLGP  [C402H22]  98.08 56.52 180 top
C151  SC10U10V5KX-2DLGP  [C805H50]  155.96 56.44 180 top
C152  SC10U10V5KX-2DLGP  [C805H50]  157.94 56.44 180 top
C153  SCD1U16V2KX-3DLGP  [C402H22]  161.96 55.24 90 top
C155  SCD1U25V2KX-GP  [C402H22]  152.81 53.47 90 top
C156  SC1U10V2KX-1DLGP  [C402H22]  104.43 52.96 90 top
C157  SCD1U16V2KX-3DLGP  [C402H22]  105.53 52.07 270 top
C158  SC22P50V2JN-4GP  [C402H22]  154.21 48.87 90 top
C159  SC1U10V2KX-1DLGP  [C402H22]  120.99 48.44 0 top
C160  SCD1U16V2KX-3DLGP  [C402H22]  121.91 48.44 0 top
C161  SC100P50V2JN-3DLGP  [C402H22]  148.95 48.11 0 top
C162  SCD1U16V2KX-3DLGP  [C402H22]  165.41 43.76 90 top
C163  SCD1U16V2KX-3DLGP  [C402H22]  161.88 43.74 270 top
C164  SC10U6D3V3MX-DL-GP  [C603H36]  151.9 43.38 90 top
C165  SC10U6D3V3MX-GP  [C603H38]  162.01 42.7 270 top
C166  SC10U6D3V3MX-DL-GP  [C603H36]  165.69 42.67 270 top
C167  SC1U10V2KX-1DLGP  [C402H22]  159.7 42.6 0 top
C168  SC100P50V2JN-3GP  [C402H22]  154.85 42.42 0 top
C169  SCD1U16V2KX-3DLGP  [C402H22]  129.74 41.54 0 top
C170  SCD1U16V2KX-3DLGP  [C402H22]  135.91 41.54 180 top
C171  SCD01U50V2KX-1DLGP  [C402H22]  136.8 41.54 180 top
C172  SC33P50V2JN-3DLGP  [C402H22]  93.02 41.22 270 top
C173  SC1KP50V2KX-1GP  [C402H22]  157.61 39.34 90 top
C174  SCD1U16V2KX-3DLGP  [C402H22]  138.96 38.69 270 top
C175  SC10U25V5KX-DL-GP  [C805H58]  41.94 37.97 90 top
C176  SCD1U16V2KX-3DLGP  [C402H22]  138.96 37.81 270 top
C177  SCD1U16V2KX-3DLGP  [C402H22]  138.96 36.89 270 top
C178  SC1U50V3KX-1-GP  [C603H36]  156.9 36.17 90 top
C179  SCD1U16V2KX-3DLGP  [C402H22]  138.96 36 270 top
C180  SCD1U50V3KX-DL-GP  [C603H35]  153.4 35.81 270 top
C181  SC10U25V5KX-DL-GP  [C805H58]  41.94 35.69 90 top
C182  SCD1U16V2KX-3DLGP  [C402H22]  138.96 35.09 270 top
C183  SCD22U25V3KX-DL-GP  [C603H36]  150.15 34.8 0 top
C184  SC100P50V2JN-3DLGP  [C402H22]  86.32 34.44 270 top
C185  SC100P50V2JN-3DLGP  [C402H22]  84.26 34.42 90 top
C186  SCD1U16V2KX-3DLGP  [C402H22]  138.96 34.2 270 top
C187  SC100P50V2JN-3DLGP  [C402H22]  160.82 34.16 270 top
C188  SCD1U16V2KX-3DLGP  [C402H22]  138.96 33.28 270 top
C189  SC1U10V2KX-1DLGP  [C402H22]  91.73 33.15 180 top
C190  SCD1U16V2KX-3GP  [C402H22]  93.63 33.15 180 top
C191  SCD027U50V3KX-DL-GP  [C603H36]  161.53 33.02 270 top
C192  SCD1U16V2KX-3DLGP  [C402H22]  138.96 32.39 270 top
C193  SCD22U25V3KX-DL-GP  [C603H36]  150.15 32 180 top
C194  SCD027U50V3KX-DL-GP  [C603H36]  161.42 31.65 270 top
C195  SCD1U16V2KX-3DLGP  [C402H22]  137.03 31 0 top
C196  SCD1U16V2KX-3DLGP  [C402H22]  133.35 30.12 270 top
C197  SC1U50V3KX-1-GP  [C603H36]  162.48 29.92 270 top
C198  SCD01U50V2KX-1DLGP  [C402H22]  37.8 29.69 180 top
C199  SCD22U25V3KX-DL-GP  [C603H36]  150.15 29.21 0 top
C200  SC1U50V3KX-1-GP  [C603H36]  162.48 28.73 270 top
C201  SCD1U25V2KX-LL-GP  [C402H22]  33.89 28.09 180 top
C202  SCD1U25V2KX-LL-GP  [C402H22]  34.78 28.09 180 top
C203  SCD1U16V2KX-3DLGP  [C402H22]  123.88 27.84 0 top
C204  SCD1U16V2KX-3DLGP  [C402H22]  103.16 27.69 90 top
C205  SCD01U50V2KX-1DLGP  [C402H22]  121.45 27.46 270 top
C206  SCD1U16V2KX-3GP  [C402H22]  41.69 27.28 90 top
C207  SC10U10V5KX-2GP  [C805H54]  97.06 26.67 0 top
C208  SC10U10V5KX-2GP  [C805H54]  99.09 26.67 0 top
C209  SCD1U16V2KX-3GP  [C402H22]  103.16 26.67 90 top
C210  SCD22U25V3KX-DL-GP  [C603H36]  151.39 26.47 270 top
C211  SCD68U16V3KX-GP-U  [C603H36]  146.74 26.42 90 top
C212  SCD68U16V3KX-GP-U  [C603H36]  143.52 26.01 270 top
C213  SCD68U16V3KX-GP-U  [C603H36]  151.19 25.25 90 top
C214  SCD68U16V3KX-GP-U  [C603H36]  148.29 25.22 270 top
C215  SCD027U50V3KX-DL-GP  [C603H36]  158.13 25.03 270 top
C216  SCD1U50V3KX-DL-GP  [C603H35]  153.55 24.54 0 top
C217  SCD027U50V3KX-DL-GP  [C603H36]  157.51 23.67 270 top
C218  SCD1U16V2KX-3DLGP  [C402H22]  154.21 20.8 270 top
C219  SCD1U16V2KX-3DLGP  [C402H22]  32.42 19.81 180 top
C220  SCD1U16V2KX-3DLGP  [C402H22]  33.31 19.81 180 top
C221  SCD01U50V2KX-1DLGP  [C402H22]  49.44 17.78 180 top
C222  SC1KP50V2KX-1DLGP  [C402H22]  145.32 15.54 180 top
C223  SC1KP50V2KX-1DLGP  [C402H22]  145.32 12.73 0 top
C224  SCD1U16V2KX-3DLGP  [C402H22]  33.05 11.38 180 top
C225  SCD1U16V2KX-3DLGP  [C402H22]  40.6 10.89 270 top
C226  SC12P50V2JN-DL-GP  [C402H22]  34.45 10.54 270 top
C227  SC15P50V2JN-DL-GP  [C402H22]  37.33 10.33 90 top
C228  SC1KP50V2KX-1DLGP  [C402H22]  145.32 10.03 180 top
C229  SC10P50V2JN-4GP  [C402H22]  30.5 8.94 180 top
C230  SC2D2U10V3KX-1DLGP-U  [C603H36]  33.38 7.32 0 top
C231  SC1KP50V2KX-1DLGP  [C402H22]  145.32 7.21 0 top
C232  SC10P50V2JN-4GP  [C402H22]  30.5 7.03 0 top
C233  SC1U10V2KX-1GP  [C402H22]  45.35 6.05 0 top
C234  SC1U10V2KX-1GP  [C402H22]  43.75 5.82 90 top
C235  SC1U10V2KX-1DLGP  [C402H22]  108.15 225.01 270 bottom
C236  SC1U6D3V2KX-DLGP  [C402H22]  106.31 223.08 270 bottom
C237  SC1KP50V2KX-1DLGP  [C402H22]  99 222.52 90 bottom
C238  SC1U6D3V2KX-DLGP  [C402H22]  106.31 222.12 270 bottom
C239  SC1KP50V2KX-1DLGP  [C402H22]  99 221.55 90 bottom
C240  SCD1U16V2KX-3DLGP  [C402H22]  97 221.55 270 bottom
C241  SCD1U16V2KX-3DLGP  [C402H22]  94.52 221.52 90 bottom
C242  SC1U10V2KX-1DLGP  [C402H22]  105.5 220 180 bottom
C243  SC4D7U6D3V2MX-1-GP  [C402H22]  93.07 219.23 270 bottom
C244  SC1U10V2KX-1GP  [C402H22]  133.89 217.17 180 bottom
C245  SCD1U16V2KX-3DLGP  [C402H22]  96.66 216.81 0 bottom
C246  SC1U10V2KX-1GP  [C402H22]  126.78 214 0 bottom
C247  SC4D7U6D3V2MX-1-GP  [C402H22]  94.44 213.78 270 bottom
C248  SC1U10V2KX-1DLGP  [C402H22]  98.39 213.68 90 bottom
C249  SC2D2U10V3KX-1DLGP-U  [C603H36]  131.99 210.06 180 bottom
C250  SCD1U16V2KX-3DLGP  [C402H22]  133.26 209.93 180 bottom
C251  SCD1U16V2KX-3DLGP  [C402H22]  22.95 208.79 90 bottom
C252  SC22U6D3V3MX-1-DL-GP  [C603H40]  86.87 203.05 0 bottom
C253  SC22U6D3V3MX-1-DL-GP  [C603H40]  85.66 203.05 0 bottom
C254  SC22U6D3V3MX-1-DL-GP  [C603H40]  84.43 203.05 0 bottom
C255  SC22U6D3V3MX-1-DL-GP  [C603H40]  83.13 203.03 0 bottom
C256  SC22U6D3V3MX-1-DL-GP  [C603H40]  81.89 203 0 bottom
C257  SC22U6D3V3MX-1-DL-GP  [C603H40]  88.83 202.26 270 bottom
C258  SC22U6D3V3MX-1-DL-GP  [C603H40]  89.39 201.04 270 bottom
C259  SC22U6D3V3MX-1-DL-GP  [C603H40]  90.08 199.8 270 bottom
C260  SCD1U16V2KX-3DLGP  [C402H22]  161.83 199.73 0 bottom
C261  SC10U10V5KX-2DLGP  [C805H50]  159.88 199.48 180 bottom
C262  SC10U10V5KX-2GP  [C805H54]  157.93 199.48 180 bottom
C263  SC22U6D3V3MX-1-DL-GP  [C603H40]  90.56 198.58 270 bottom
C264  SC22U6D3V3MX-1-DL-GP  [C603H40]  90.56 197.31 270 bottom
C265  SC1U10V2KX-1DLGP  [C402H22]  62.07 195.3 0 bottom
C266  SC1U10V2KX-1DLGP  [C402H22]  61.09 195.3 0 bottom
C267  SC1U10V2KX-1DLGP  [C402H22]  60.21 195.29 0 bottom
C268  SC1U10V2KX-1DLGP  [C402H22]  63 195.28 0 bottom
C269  SC22U6D3V3MX-1-DL-GP  [C603H40]  65.71 194.73 270 bottom
C270  SC22U6D3V3MX-1-DL-GP  [C603H40]  65.7 193.53 270 bottom
C271  SC22U6D3V3MX-1-DL-GP  [C603H40]  65.71 192.31 270 bottom
C272  SC22U6D3V3MX-1-DL-GP  [C603H40]  65.71 191.04 270 bottom
C273  SC22U6D3V3MX-1-DL-GP  [C603H40]  65.71 189.77 270 bottom
C274  SCD1U16V2KX-3DLGP  [C402H22]  137.96 188.93 90 bottom
C275  SCD1U16V2KX-3DLGP  [C402H22]  140.29 187.2 0 bottom
C276  SC22U6D3V5MX-2DLGP  [C805H54]  53.88 186.31 90 bottom
C277  SC22U6D3V3MX-1-DL-GP  [C603H40]  53.88 184.66 90 bottom
C278  SC22U6D3V3MX-1-DL-GP  [C603H40]  53.88 183.39 90 bottom
C279  SC22U6D3V3MX-1-DL-GP  [C603H40]  53.87 182.16 90 bottom
C280  SC1U10V2KX-1DLGP  [C402H22]  84.74 181.41 270 bottom
C281  SCD1U10V2KX-5GP  [C402H22]  138.26 181.13 90 bottom
C282  SC1U10V2KX-1DLGP  [C402H22]  78.85 181.08 270 bottom
C283  SC1U10V2KX-1DLGP  [C402H22]  83.9 180.1 270 bottom
C284  SC22U6D3V3MX-1-DL-GP  [C603H40]  70.17 178.81 0 bottom
C285  SCD1U16V2KX-3GP  [C402H22]  138.36 177.34 90 bottom
C286  SC1U10V2KX-1DLGP  [C402H22]  87.33 176.9 270 bottom
C287  SC1U10V2KX-1DLGP  [C402H22]  87.4 175.53 270 bottom
C288  SC22U6D3V3MX-1-DL-GP  [C603H40]  69.92 175.07 180 bottom
C289  SCD1U16V2KX-3DLGP  [C402H22]  136.23 173.33 180 bottom
C290  SCD1U16V2KX-3DLGP  [C402H22]  132.13 173.32 180 bottom
C291  SC10U6D3V3MX-DL-GP  [C603H36]  127.74 173.3 180 bottom
C292  SC10U6D3V3MX-DL-GP  [C603H36]  130.63 173.28 180 bottom
C293  SC10U6D3V3MX-DL-GP  [C603H36]  129.24 173.22 180 bottom
C294  SC1U10V2KX-1DLGP  [C402H22]  83.71 171.62 270 bottom
C295  SC1U10V2KX-1DLGP  [C402H22]  83.28 170.13 180 bottom
C296  SC1U10V2KX-1DLGP  [C402H22]  85.54 170.09 180 bottom
C297  SC1U10V2KX-1DLGP  [C402H22]  84.15 169.77 180 bottom
C298  SC1U10V2KX-1DLGP  [C402H22]  80.5 169.74 180 bottom
C299  SC1U10V2KX-1DLGP  [C402H22]  81.87 169.7 180 bottom
C300  SC1U10V2KX-1DLGP  [C402H22]  86.34 168.17 0 bottom
C301  SC1U10V2KX-1DLGP  [C402H22]  84.64 167.75 90 bottom
C302  SC22U6D3V3MX-1-DL-GP  [C603H40]  82.05 167.27 180 bottom
C303  SC22U6D3V3MX-1-DL-GP  [C603H40]  80.2 166.91 180 bottom
C304  SC1U10V2KX-1DLGP  [C402H22]  84.66 166.86 90 bottom
C305  SC1U10V2KX-1DLGP  [C402H22]  84.02 165.45 270 bottom
C306  SC1U10V2KX-1DLGP  [C402H22]  82.62 164.98 0 bottom
C307  SC1U10V2KX-1DLGP  [C402H22]  81.22 164.98 0 bottom
C308  SC1U10V2KX-1DLGP  [C402H22]  86.62 164.94 0 bottom
C309  SC1U10V2KX-1DLGP  [C402H22]  85.23 164.56 270 bottom
C310  SC22U6D3V3MX-1-DL-GP  [C603H40]  76.82 164.21 90 bottom
C311  SCD1U16V2KX-3DLGP  [C402H22]  130.4 163.87 270 bottom
C312  SC1U10V2KX-1DLGP  [C402H22]  86.3 162.67 0 bottom
C313  SC1U10V2KX-1DLGP  [C402H22]  84.83 162.66 0 bottom
C314  SC10U6D3V3MX-DL-GP  [C603H36]  139.89 162.38 90 bottom
C315  SC1U10V2KX-1DLGP  [C402H22]  81.46 162.2 270 bottom
C316  SC10U6D3V3MX-DL-GP  [C603H36]  139.9 161.15 90 bottom
C317  SC1U10V2KX-1DLGP  [C402H22]  83.32 161.07 0 bottom
C318  SC1U10V2KX-1DLGP  [C402H22]  80.25 160.69 270 bottom
C319  SC1U10V2KX-1DLGP  [C402H22]  85.61 160.69 90 bottom
C320  SC1U10V2KX-1DLGP  [C402H22]  84.19 160.26 0 bottom
C321  SCD1U16V2KX-3DLGP  [C402H22]  139.79 160.09 90 bottom
C322  SC1U10V2KX-1DLGP  [C402H22]  85.48 159.27 0 bottom
C323  SC1U10V2KX-1DLGP  [C402H22]  82.63 159.17 0 bottom
C324  SC1U10V2KX-1DLGP  [C402H22]  79.29 158.97 90 bottom
C325  SC1U10V2KX-1DLGP  [C402H22]  91.02 158.92 180 bottom
C326  SC1U10V2KX-1DLGP  [C402H22]  76.72 158.72 180 bottom
C327  SC1U10V2KX-1DLGP  [C402H22]  81.23 158.22 180 bottom
C328  SC1U10V2KX-1DLGP  [C402H22]  78.86 158.1 90 bottom
C329  SCD1U16V2KX-3DLGP  [C402H22]  89.34 157.68 90 bottom
C330  SC1U10V2KX-1DLGP  [C402H22]  73.49 157.51 180 bottom
C331  SC1U10V2KX-1DLGP  [C402H22]  90.93 156.41 0 bottom
C332  SCD1U16V2KX-3DLGP  [C402H22]  130.18 156.15 270 bottom
C333  SC1U10V2KX-1DLGP  [C402H22]  80.31 150.73 270 bottom
C334  SC1U10V2KX-1DLGP  [C402H22]  78.39 150.1 90 bottom
C335  SC10U6D3V3MX-DL-GP  [C603H36]  129.78 149.66 0 bottom
C336  SC10U6D3V3MX-DL-GP  [C603H36]  128.56 149.65 0 bottom
C337  SC10U6D3V3MX-DL-GP  [C603H36]  136 149.63 0 bottom
C338  SCD1U16V2KX-3DLGP  [C402H22]  131.94 149.53 0 bottom
C339  SCD1U16V2KX-3DLGP  [C402H22]  130.97 149.53 0 bottom
C340  SC1U10V2KX-1DLGP  [C402H22]  88.26 148.73 90 bottom
C341  SCD1U16V2KX-3DLGP  [C402H22]  138.54 147.14 90 bottom
C342  SCD1U16V2KX-3DLGP  [C402H22]  138.51 142.85 90 bottom
C343  SCD1U16V2KX-3GP  [C402H22]  129.6 128.4 180 bottom
C344  SCD1U16V2KX-3DLGP  [C402H22]  128.68 128.4 0 bottom
C345  SC1U10V2KX-1DLGP  [C402H22]  132.52 128.37 180 bottom
C346  SC1U10V2KX-1DLGP  [C402H22]  131.61 128.37 180 bottom
C347  SC1U10V2KX-1DLGP  [C402H22]  138.59 128.12 180 bottom
C348  SC10U6D3V3MX-DL-GP  [C603H36]  135.88 127.99 0 bottom
C349  SC10U6D3V3MX-DL-GP  [C603H36]  134.61 127.99 0 bottom
C350  SC22U6D3V5MX-2DLGP  [C805H54]  74.05 119.56 0 bottom
C351  SC10U6D3V3MX-DL-GP  [C603H36]  76.54 116.31 0 bottom
C352  SC4D7U6D3V3KX-DLGP  [C603H36]  75.27 116.31 180 bottom
C353  SCD1U16V2KX-3DLGP  [C402H22]  48.25 116.28 90 bottom
C354  SCD1U16V2KX-3DLGP  [C402H22]  43.7 114.08 0 bottom
C355  SCD1U16V2KX-3DLGP  [C402H22]  42.8 114.08 0 bottom
C356  SCD22U10V2KX-2-GP  [C402H22]  87.21 113.82 180 bottom
C357  SCD22U10V2KX-2-GP  [C402H22]  86.32 113.82 180 bottom
C358  SCD22U10V2KX-2-GP  [C402H22]  89.06 113.79 180 bottom
C359  SCD22U10V2KX-2-GP  [C402H22]  88.17 113.79 180 bottom
C360  SC10U6D3V3MX-DL-GP  [C603H36]  41.77 113.72 0 bottom
C361  SC10U6D3V3MX-DL-GP  [C603H36]  40.59 113.72 0 bottom
C362  SC10U10V5KX-2DLGP  [C805H50]  80.88 113.44 270 bottom
C363  SC10U6D3V3MX-DL-GP  [C603H36]  76.74 112.9 270 bottom
C364  SCD022U16V2KX-3DLGP  [C402H22]  36.38 113.63 0 bottom
C365  SC10U10V5KX-2DLGP  [C805H50]  80.88 111.4 270 bottom
C366  SC10U6D3V3MX-DL-GP  [C603H36]  75.66 111.21 270 bottom
C367  SC22U6D3V5MX-2DLGP  [C805H54]  96.32 110.57 180 bottom
C368  SC1U50V3KX-1-GP  [C603H36]  76.66 109.88 270 bottom
C369  SC1U10V2KX-1DLGP  [C402H22]  37.49 115.04 90 bottom
C370  SC10U6D3V3MX-DL-GP  [C603H36]  76.66 108.71 270 bottom
C371  SCD1U16V2KX-3DLGP  [C402H22]  63.2 108.67 180 bottom
C372  SCD1U16V2KX-3DLGP  [C402H22]  48.29 108.5 90 bottom
C373  SC1U50V3KX-1-GP  [C603H36]  79.26 107.54 90 bottom
C374  SCD1U16V2KX-3DLGP  [C402H22]  82.15 107.42 0 bottom
C375  SC4D7U6D3V3KX-DLGP  [C603H36]  92.87 107.04 180 bottom
C376  SC4D7U6D3V3KX-DLGP  [C603H36]  91.68 107.04 180 bottom
C377  SCD1U16V2KX-3DLGP  [C402H22]  89.2 106.73 0 bottom
C378  SC4D7U6D3V3KX-DLGP  [C603H36]  75.79 106.22 270 bottom
C379  SC1U10V2KX-1DLGP  [C402H22]  84.15 105.76 0 bottom
C380  SC1U10V2KX-1DLGP  [C402H22]  80.09 105.3 90 bottom
C381  SC1U10V2KX-1DLGP  [C402H22]  78.16 105.3 270 bottom
C382  SC1U10V2KX-1DLGP  [C402H22]  89.76 104.88 270 bottom
C383  SC1U10V2KX-1DLGP  [C402H22]  88.34 104.87 0 bottom
C384  SC1U10V2KX-1DLGP  [C402H22]  48.46 104.55 90 bottom
C385  SC1U50V3KX-1-GP  [C603H36]  79.03 85.24 270 bottom
C386  SC4D7U6D3V3KX-DLGP  [C603H36]  90.13 103.84 90 bottom
C387  SC1U50V3KX-1-GP  [C603H36]  74.35 103.73 270 bottom
C388  SC4D7U6D3V3KX-DLGP  [C603H36]  82.66 103.5 90 bottom
C389  SC1U10V2KX-1DLGP  [C402H22]  76.71 103.42 180 bottom
C390  SC4D7U6D3V3KX-DLGP  [C603H36]  86.49 103.27 180 bottom
C391  SC22U6D3V5MX-2DLGP  [C805H54]  37.65 103.15 0 bottom
C392  SC1U10V2KX-1DLGP  [C402H22]  84.61 103.02 0 bottom
C393  SC4D7U6D3V3KX-DLGP  [C603H36]  89.16 102.64 90 bottom
C394  SC22U6D3V5MX-2DLGP  [C805H54]  79.52 102.59 90 bottom
C395  SC47U6D3V5MX-1DL-GP  [C805H54]  94.52 102.57 0 bottom
C396  SC10U10V5KX-2DLGP  [C805H50]  40.44 102.49 270 bottom
C397  SCD1U16V2KX-3DLGP  [C402H22]  35.69 101.77 90 bottom
C398  SC4D7U6D3V3KX-DLGP  [C603H36]  82.65 101.49 90 bottom
C399  SC4D7U6D3V3KX-DLGP  [C603H36]  89.95 101.45 90 bottom
C400  SC10U6D3V3MX-DL-GP  [C603H36]  92.77 101.3 0 bottom
C401  SC10U10V5KX-2DLGP  [C805H50]  32.16 101.22 270 bottom
C402  SCD1U16V2KX-3DLGP  [C402H22]  40.06 101.07 90 bottom
C403  SCD1U16V2KX-3DLGP  [C402H22]  91.73 100.93 0 bottom
C404  SCD1U16V2KX-3DLGP  [C402H22]  35.69 100.89 90 bottom
C405  SC47U6D3V5MX-1DL-GP  [C805H54]  79.48 100.6 90 bottom
C406  SC4D7U6D3V3KX-DLGP  [C603H36]  85.47 100.4 270 bottom
C407  SC4D7U6D3V3KX-DLGP  [C603H36]  88.2 100.25 90 bottom
C408  SC4D7U6D3V3KX-DLGP  [C603H36]  82.65 99.51 90 bottom
C409  SC4D7U6D3V3KX-DLGP  [C603H36]  88.2 99.06 90 bottom
C410  SCD1U16V2KX-3DLGP  [C402H22]  91.68 98.95 180 bottom
C411  SC22U6D3V5MX-2DLGP  [C805H54]  94.52 98.78 0 bottom
C412  SCD1U16V2KX-3DLGP  [C402H22]  77.62 98.67 180 bottom
C413  SC4D7U6D3V3KX-DLGP  [C603H36]  85.45 98.55 270 bottom
C414  SC4D7U6D3V3KX-DLGP  [C603H36]  79.45 98.47 270 bottom
C415  SCD1U16V2KX-3DLGP  [C402H22]  31.53 97.79 270 bottom
C416  SCD1U16V2KX-3DLGP  [C402H22]  92.57 97.69 0 bottom
C417  SCD1U16V2KX-3DLGP  [C402H22]  89.82 97.05 90 bottom
C418  SCD1U16V2KX-3DLGP  [C402H22]  31.53 96.9 270 bottom
C419  SCD1U16V2KX-3DLGP  [C402H22]  75.14 96.67 180 bottom
C420  SC4D7U6D3V3KX-DLGP  [C603H36]  79.91 96.64 270 bottom
C421  SC4D7U6D3V3KX-DLGP  [C603H36]  85.94 96.44 90 bottom
C422  SC4D7U6D3V3KX-DLGP  [C603H36]  83.24 96.44 90 bottom
C423  SCD1U16V2KX-3DLGP  [C402H22]  31.53 96.01 270 bottom
C424  SC1U10V2KX-1DLGP  [C402H22]  73.44 95.92 0 bottom
C425  SC4D7U6D3V3KX-DLGP  [C603H36]  92.9 95.38 180 bottom
C426  SC1U50V3KX-1-GP  [C603H36]  91.68 95.38 0 bottom
C427  SCD1U16V2KX-3DLGP  [C402H22]  88.37 95.35 0 bottom
C428  SCD1U16V2KX-3DLGP  [C402H22]  90.15 95.34 0 bottom
C429  SCD1U16V2KX-3DLGP  [C402H22]  89.26 95.34 0 bottom
C430  SC4D7U6D3V3KX-DLGP  [C603H36]  81.33 95.25 270 bottom
C431  SCD1U16V2KX-3DLGP  [C402H22]  31.53 95.12 270 bottom
C432  SC1U10V2KX-1DLGP  [C402H22]  83.14 94.89 180 bottom
C433  SC1U50V3KX-1-GP  [C603H36]  85.2 94.61 90 bottom
C434  SCD1U16V2KX-3DLGP  [C402H22]  77.5 94.13 180 bottom
C435  SCD1U16V2KX-3DLGP  [C402H22]  79.69 93.68 270 bottom
C436  SCD1U16V2KX-3DLGP  [C402H22]  81.79 93.39 0 bottom
C437  SC1U10V2KX-1DLGP  [C402H22]  63.68 93.21 270 bottom
C438  SCD1U16V2KX-3DLGP  [C402H22]  31.53 93.09 270 bottom
C439  SC1U10V2KX-1DLGP  [C402H22]  48.29 92.96 90 bottom
C440  SC4D7U6D3V3KX-DLGP  [C603H36]  86.7 92.68 0 bottom
C442  SCD1U16V2KX-3DLGP  [C402H22]  31.53 92.2 270 bottom
C443  SCD1U16V2KX-3DLGP  [C402H22]  63.17 90.75 180 bottom
C444  SCD1U16V2KX-3DLGP  [C402H22]  48.34 89.99 90 bottom
C445  SCD1U16V2KX-3DLGP  [C402H22]  33.51 89.56 90 bottom
C446  SC4D7U6D3V3KX-DLGP  [C603H36]  74.23 89.28 180 bottom
C447  SC10U6D3V3MX-DL-GP  [C603H36]  79.72 89.23 270 bottom
C448  SCD1U16V2KX-3DLGP  [C402H22]  37.45 89.03 180 bottom
C449  SCD1U16V2KX-3DLGP  [C402H22]  33.51 88.62 90 bottom
C450  SCD01U25V2KX-3LLGP  [C402H22]  45.93 87.26 0 bottom
C451  SC1U10V2KX-1GP  [C402H22]  38.64 86.49 180 bottom
C452  SC1U10V2KX-1GP  [C402H22]  34.07 86.49 180 bottom
C453  SC1U10V2KX-1GP  [C402H22]  31.52 86.08 90 bottom
C454  SC1U10V2KX-1DLGP  [C402H22]  63.7 85.78 270 bottom
C455  SC10U6D3V3MX-DL-GP  [C603H36]  48.5 84.48 90 bottom
C456  SC4D7U6D3V3KX-DLGP  [C603H36]  79.03 84.05 90 bottom
C457  SC1U10V2KX-1GP  [C402H22]  31.53 83.06 90 bottom
C458  SC10U25V5KX-DL-GP  [C805H58]  79.23 82.47 270 bottom
C459  SCD1U16V2KX-3DLGP  [C402H22]  32.34 82.16 90 bottom
C460  SCD1U16V2KX-3DLGP  [C402H22]  32.34 81.27 270 bottom
C461  SC10U10V5KX-2DLGP  [C805H50]  32.51 79.85 270 bottom
C462  SC1U10V2KX-1DLGP  [C402H22]  39.3 77.04 0 bottom
C463  SCD1U16V2KX-3DLGP  [C402H22]  139.4 74.34 0 bottom
C464  SC2D2U10V3KX-1GP  [C603H36]  127.13 70.5 90 bottom
C465  SCD01U50V2KX-1DLGP  [C402H22]  48.91 67.86 90 bottom
C466  SC1U6D3V2KX-GP  [C402H22]  133.66 67.5 90 bottom
C467  SCD1U10V2KX-5GP  [C402H22]  126.31 67.28 180 bottom
C468  SCD1U16V2KX-3DLGP  [C402H22]  121.83 65.41 90 bottom
C469  SC100P50V2JN-3DLGP  [C402H22]  126.67 63.88 270 bottom
C470  SCD1U16V2KX-3DLGP  [C402H22]  126.67 62.98 270 bottom
C471  SC100P50V2JN-3DLGP  [C402H22]  130.66 62.77 270 bottom
C472  SCD1U16V2KX-3DLGP  [C402H22]  130.66 61.89 270 bottom
C473  SC2D2U10V3KX-1DLGP-U  [C603H36]  121.15 59.99 0 bottom
C474  SCD1U16V2KX-3DLGP  [C402H22]  116.62 58.4 0 bottom
C475  SC1KP50V2KX-1DLGP  [C402H22]  106.41 58.19 90 bottom
C476  SCD1U16V2KX-3DLGP  [C402H22]  131.43 57.78 0 bottom
C477  SCD1U16V2KX-3DLGP  [C402H22]  130.49 57.78 0 bottom
C478  SC1KP50V2KX-1DLGP  [C402H22]  106.41 57.23 90 bottom
C479  SC10U10V5KX-2DLGP  [C805H50]  160.46 56.59 0 bottom
C480  SC10U10V5KX-2DLGP  [C805H50]  158.48 56.57 180 bottom
C481  SC10U10V5KX-2GP  [C805H54]  105.6 53.68 90 bottom
C482  SC1U10V2KX-1GP  [C402H22]  152.2 48.59 180 bottom
C483  SCD1U16V2KX-3DLGP  [C402H22]  156.98 48.11 90 bottom
C484  SC10U6D3V3MX-DL-GP  [C603H36]  157.31 47.02 90 bottom
C485  SC1U50V3KX-1-GP  [C603H36]  161.07 45.77 90 bottom
C486  SCD1U16V2KX-3DLGP  [C402H22]  154.31 44.37 180 bottom
C487  SC10U6D3V3MX-DL-GP  [C603H36]  153.17 43.99 0 bottom
C488  SC10U6D3V3MX-GP  [C603H38]  156.12 43.48 90 bottom
C489  SCD1U16V2KX-3GP  [C402H22]  156.45 42.42 90 bottom
C490  SCD01U50V2KX-1DLGP  [C402H22]  135.79 41.54 0 bottom
C491  SCD01U50V2KX-1DLGP  [C402H22]  129.69 41.54 0 bottom
C492  SC1U100V6KX-LL-GP  [C1206H71]  24.16 40.34 0 bottom
C493  SC1U100V6KX-3-GP  [C1206H75]  27.36 40.31 0 bottom
C494  SCD1U25V3ZY-1-LL-GP  [C603H36]  48.42 39.62 180 bottom
C495  SCD1U16V2KX-3DLGP  [C402H22]  118.4 39.37 180 bottom
C496  SC1U100V6KX-3-GP  [C1206H75]  24.16 35.69 180 bottom
C497  SC1U100V6KX-3-GP  [C1206H75]  27.36 35.66 180 bottom
C498  SC100P50V2JN-3DLGP  [C402H22]  36.41 35 180 bottom
C499  SC1U100V6KX-3-GP  [C1206H75]  30.92 34.85 270 bottom
C500  SC10U25V5KX-DL-GP  [C805H58]  153.2 32.51 180 bottom
C501  SC10U10V5KX-2DLGP  [C805H50]  38.87 32.05 90 bottom
C502  SC1KP50V2KX-1DLGP  [C402H22]  63.53 30.73 270 bottom
C503  SCD01U50V2KX-1DLGP  [C402H22]  126.32 30.56 90 bottom
C504  SCD01U50V2KX-1DLGP  [C402H22]  38.51 29.84 270 bottom
C505  SCD1U16V2KX-3DLGP  [C402H22]  27.36 29.16 90 bottom
C506  SC10U25V5KX-DL-GP  [C805H58]  153.2 28.83 180 bottom
C507  SC1KP50V2KX-1DLGP  [C402H22]  38.51 28.65 270 bottom
C508  SCD1U16V2KX-3DLGP  [C402H22]  25.97 27.56 180 bottom
C509  SC1U16V3KX-2GP  [C603H36]  154.9 25.65 270 bottom
C510  SCD1U16V2KX-3DLGP  [C402H22]  25.94 25.6 0 bottom
C511  SCD1U16V2KX-3GP  [C402H22]  38.13 25.4 90 bottom
C512  SC27P50V2JN-2-LL-GP  [C402H22]  38.13 24.51 90 bottom
C513  SC1U10V2KX-1DLGP  [C402H22]  35.03 24.31 180 bottom
C514  SCD1U16V2KX-3GP  [C402H22]  24.49 24 90 bottom
C515  SCD47U25V3KX-1-DL-GP  [C603H36]  32.06 23.9 90 bottom
C516  SC100P50V2JN-3DLGP  [C402H22]  26.82 23.06 270 bottom
C517  SC1U10V2KX-1GP  [C402H22]  31.2 19.91 0 bottom
C519  SC10U10V5KX-2DLGP  [C805H50]  120.18 18.92 270 bottom
C520  SC4D7U6D3V3KX-GP  [C603H36]  34.22 17.44 270 bottom
C521  SCD1U16V2KX-3DLGP  [C402H22]  36.89 17.16 0 bottom
C522  SCD1U16V2KX-3DLGP  [C402H22]  36.01 17.16 180 bottom
C523  SC4D7U6D3V3KX-GP  [C603H36]  38.01 16.76 180 bottom
C524  SCD1U16V2KX-3GP  [C402H22]  34.47 16.41 270 bottom
C525  SCD01U50V3KX-4GP  [C603H36]  145.47 16.33 90 bottom
C526  SCD1U16V2KX-3DLGP  [C402H22]  39.56 15.65 270 bottom
C527  SCD1U16V2KX-3DLGP  [C402H22]  34.48 15.5 90 bottom
C528  SCD1U16V2KX-3DLGP  [C402H22]  39.56 14.76 270 bottom
C529  SCD1U16V2KX-3DLGP  [C402H22]  34.47 14.63 90 bottom
C530  SC4D7U6D3V3KX-GP  [C603H36]  31.5 13.79 90 bottom
C531  SCD1U16V2KX-3DLGP  [C402H22]  34.97 13.58 270 bottom
C532  SC1U50V3KX-1-GP  [C603H36]  38.78 12.99 0 bottom
C533  SCD1U16V2KX-3DLGP  [C402H22]  37.74 12.77 180 bottom
C534  SCD1U16V2KX-3DLGP  [C402H22]  36.85 12.77 180 bottom
C535  SCD1U16V2KX-3DLGP  [C402H22]  31.66 12.64 90 bottom
C536  SC1U50V3KX-1-GP  [C603H36]  34.97 12.4 270 bottom
C537  SCD1U16V2KX-3DLGP  [C402H22]  30.18 12.24 180 bottom
C538  SCD01U50V3KX-4GP  [C603H36]  145.47 12.14 90 bottom
C539  SCD1U16V2KX-3DLGP  [C402H22]  31.66 11.73 90 bottom
C540  SCD01U50V3KX-4GP  [C603H36]  145.47 10.87 90 bottom
C541  SC4D7U6D3V3KX-GP  [C603H36]  40.5 10.2 180 bottom
C542  SC2D2U10V3KX-1DLGP-U  [C603H36]  27.99 9.9 180 bottom
C543  SCD1U16V2KX-3DLGP  [C402H22]  39.04 9.88 0 bottom
C544  SC1U10V2KX-1GP  [C402H22]  43.98 9.45 270 bottom
C545  SCD01U50V3KX-4GP  [C603H36]  145.65 7.72 90 bottom
C546  SC10U10V5KX-2DLGP  [C805H50]  27.77 6.76 0 bottom
C547  SCD1U16V2KX-3DLGP  [C402H22]  95.94 107.4 0 bottom
C548  SC4D7U6D3V3KX-DLGP  [C603H36]  37.7 106.86 90 bottom
C549  SC1KP50V2KX-1DLGP  [C402H22]  94.28 160.73 270 bottom
C550  SC1KP50V2KX-1DLGP  [C402H22]  142.81 154.39 180 bottom
C551  SC1KP50V2KX-1DLGP  [C402H22]  154.99 166.5 270 bottom
C552  SC1KP50V2KX-1DLGP  [C402H22]  94.85 182.32 0 bottom
